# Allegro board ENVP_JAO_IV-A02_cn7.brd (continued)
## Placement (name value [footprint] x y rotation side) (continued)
U124  28 PINP LM5176RHFR  [VQFN28F-5X4X1M]  32.35 106.35 0 top
U126  PP4B10BK,  [TS-MOSFET5X6X1P2]  28.19 118.55 90 top
U127  TPS7B8533QWDRCRQ1  [VSON10F-3X3X1M]  46.55 109.22 180 top

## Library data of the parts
C40-C43 C50-C52 C57 C58 C64 C70-C73 C76 C77 C82 C84 C122 C125 C126 C396-C403 C408 C412-C426 C472 C497 C500-C516 C568 C569 C604 C605 C618-C622 C635 C636 = 11-CAP1-2P0: Tolerance: TOL**; User Part Number: USER**
C44 C45 C498 C499 = 11-CAP-2P0: Tolerance: TOL**; User Part Number: USER**
C46-C49 C55 C56 C59-C63 C65-C69 C104-C117 C119-C121 C123 C124 C244 C380 C382 C454 C456 C457 C459 C461 C466-C468 C471 C473 C475-C478 C489 = 11-CAP1-2P0: User Part Number: USER**; Tolerance: TOL**
C53 C54 C103 C118 C495 C496 = 11-CAP-2P0: User Part Number: USER**; Tolerance: TOL**
CN1 = 1652-PC-3P-ECH381RM03PBK: User Part Number: USER**; Tolerance: TOL**
CN19 = 1653-PH-4P*1-0: User Part Number: USER**; Tolerance: TOL**
CN35 = HL-VGA-9MX2
D1 = 130-S2P-SS1060HEWS-0: User Part Number: USER**; Tolerance: TOL**
D2 = 130-S2P-PMEG2010AEB-0: Tolerance: TOL**; User Part Number: USER**
D3 = 130-S2P-SBM56LAFC-0: User Part Number: USER**; Tolerance: TOL**
D4 = 130-S3P-BAT54CW-0: Tolerance: TOL**; User Part Number: USER**
D6 D7 D49 = 130-E_D2P-TV50C360JBCRHF-0: User Part Number: USER**; Tolerance: TOL**
D9 D13 = 130-D2P-1N4148WS-0: User Part Number: USER**; Tolerance: TOL**
D28 D29 = 130-S2P-SBM56LAFC-0: Tolerance: TOL**; User Part Number: USER**
D31 = 130-S2P-SS1060HEWS-0: Tolerance: TOL**; User Part Number: USER**
D50-D59 = SMBJ18CA: Tolerance: TOL**; User Part Number: USER**
FB1 = 121-FB-2P: User Part Number: USER**; Tolerance: TOL**
H2 = MH: User Part Number: USER**; Tolerance: TOL**
HM3 = S-SO-MH276D167-PTH: User Part Number: USER**; Tolerance: TOL**
L1 L3 L4 = 121-L_COIL-2P: User Part Number: USER**; Tolerance: TOL**
L6 L40 L41 = 121-L_COIL-2P: Tolerance: TOL**; User Part Number: USER**
M2 = S-SO-MH197D138-1-PTH: Tolerance: TOL**; User Part Number: USER**
NOREF NOREF#4 NOREF#6 NOREF#7 = -: User Part Number: USER**; Tolerance: TOL**
NOREF#2 = -: Tolerance: TOL**; User Part Number: USER**
Q3 Q4 Q8 Q17 Q40 Q41 Q52 Q67 = 131-N_MOS3P-NTS4001N-0: User Part Number: USER**; Tolerance: TOL**
Q6 = 131-PN_MOS8P-P0706BK: User Part Number: USER**; Tolerance: TOL**
Q7 = 131-PN_MOS8P-P0706BK: Tolerance: TOL**; User Part Number: USER**
Q9 Q15 Q16 Q18-Q20 Q38 = 131-N_MOS3P-NTS4001N-0: Tolerance: TOL**; User Part Number: USER**
Q12 Q13 = 131-D_N8P-BSC0925ND-0: User Part Number: USER**; Tolerance: TOL**
Q14 = 131-N_MOS6P-PJX138KAR100001-0: User Part Number: USER**; Tolerance: TOL**
Q21 Q62 Q63 = 131-PP_MOS8P-FDS6681Z-0: User Part Number: USER**; Tolerance: TOL**
Q64 Q68 = 131-N_MOS9P-PG1H10ATL: Tolerance: TOL**; User Part Number: USER**
Q65 = 131-N_MOS8P-P0406AK-0: Tolerance: TOL**; User Part Number: USER**
Q66 = 131-NPN3P-MMBT3904W-0: Tolerance: TOL**; User Part Number: USER**
Q73 = 131-N_MOS8P-DMT10H015LCG-0: Tolerance: TOL**; User Part Number: USER**
R23 R24 R27-R29 R37 R41 R43 R44 R50 R51 R63 R64 R66-R70 R97 R112 R113 R119 R339 R425 R457 R459 R469 R470 R477 R479 R497 R501-R503 R513 R515 R521-R527 R529 R546-R561 R687-R704 R706-R708 R782 R801 R803 R815 R841-R845 R848-R851 = 10-R: Tolerance: TOL**; User Part Number: USER**
R30-R36 R38-R40 R42 R45-R49 R52-R61 R72 R73 R91-R96 R98-R111 R114-R118 R120-R122 R304 R455 R462 R463 R480 R481 R608 R610 R612 R617 R620 R624 R625 R649 R651-R658 R663 R665 R667 R671 R674 R682 R705 R738 R739 R758-R760 = 10-R: User Part Number: USER**; Tolerance: TOL**
TP32-TP34 TP98 = TestPoint: Tolerance: TOL**; User Part Number: USER**
TP36 TP48 TP49 TP54-TP59 TP62 TP66 TP67 TP91 TP92 TP101 = TestPoint: User Part Number: USER**; Tolerance: TOL**
U2 = 14-P_R-MIC2128YMLTR-0: User Part Number: USER**; Tolerance: TOL**
U3 U117 = 14-P_R-MP2384GG-0: User Part Number: USER**; Tolerance: TOL**
U8 = 14-P_R-LM5176RHFR-0: User Part Number: USER**; Tolerance: TOL**
U77 = 14-T_C_L-SN74LVC1G11DCKR-0: Tolerance: TOL**; User Part Number: USER**
U97 U99 = 14-T_C_L-SN74AUP1G04DRLR-0: Tolerance: TOL**; User Part Number: USER**
U98 U100 U101 = 14-T_C_L-SN74LVC1G126DCKR-0: User Part Number: USER**; Tolerance: TOL**
U102 U104 = 14-T_C_L-SN74LVC1G11DCKR-0: User Part Number: USER**; Tolerance: TOL**
U103 = 14-T_C_L-74LVC1G86SE-7: User Part Number: USER**; Tolerance: TOL**
U107 = CYPD4226-40LQXIT: Tolerance: TOL**; User Part Number: USER**
U108 = 14-P_R-TPS2051BDBVR-0: User Part Number: USER**; Tolerance: TOL**
U124 = 14-P_R-LM5176RHFR-0: Tolerance: TOL**; User Part Number: USER**
U126 = 131-N_MOS8P-PP4B10BK-0: Tolerance: TOL**; User Part Number: USER**
U127 = TPS7B8533QWDRCRQ1: Tolerance: TOL**; User Part Number: USER**

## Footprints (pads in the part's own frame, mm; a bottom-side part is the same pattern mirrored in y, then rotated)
C0402
  oval 0.61x0.711 smd: 1(-0.457,0) 2(0.457,0)
C0402_PLUS
  oval 0.61x0.711 smd: 1(-0.457,0) 2(0.457,0)
C0603
  rect 0.889x1.016 smd: 1(-0.775,0) 2(0.775,0)
C0805
  rect 1.016x1.524 smd: 1(-0.914,0) 2(0.914,0)
C1206
  oval 1.067x1.803 smd: 1(-1.524,0) 2(1.524,0)
C1210
  oval 1.067x2.692 smd: 1(-1.524,0) 2(1.524,0)
C1808
  oval 1.372x2.21 smd: 1(-2.021,0) 2(2.022,0)
CD8P35-1
  rect 1.422x1.422 hole 0.914: 1(-1.75,0)
  round 1.422 hole 0.914: 2(1.75,0)
DB_HL-VGA9MX2-H28_43MM
  rect 1.6x1.6 hole 1.092: 1(-5.54,9.75) 10(-5.54,2.84)
  round 1.6 hole 1.092: 2(-2.77,9.75) 3(0,9.75) 4(2.77,9.75) 5(5.54,9.75) 6(-4.155,6.91) 7(-1.385,6.91) 8(1.385,6.91) 9(4.155,6.91) 11(-2.77,2.84) 12(0,2.84) 13(2.77,2.84) 14(5.54,2.84) 15(-4.155,0) 16(-1.385,0) 17(1.385,0) 18(4.155,0)
  round 3.708 hole 3.2: H1(-12.495,8) H2(12.495,8) H3(-12.495,0) H4(12.495,0)
DFN8E-3P3X3P3X0P85M
  rect 0.432x0.711 smd: 1(-0.975,-1.406) 2(-0.325,-1.406) 3(0.325,-1.406) 4(0.975,-1.406)
  custom 0.538x0.538 smd: 5(0,0)
ESD-2P-SMA
  rect 1.397x1.651 smd: 1(-2.015,0) 2(2.015,0)
JH4-HD
  rect 1.397x1.397 hole 0.889: 1(-3.81,0)
  round 1.397 hole 0.889: 2(-1.27,0) 3(1.27,0) 4(3.81,0)
L1206
  oval 1.067x1.803 smd: 1(-1.524,0) 2(1.524,0)
MH197D138-1
  round 5.004 hole 3.505: 1(0,0)
MH217D138
  round 5.512 hole 3.505: 1(0,0)
MH276D150-T4P05M
  round 4.699 hole 3.81: 1(0,0)
QFN11F-2X2X1M
  rect 1.499x0.254 smd: 1(-0.55,0.25) 6(0.55,-0.25)
  rect 0.254x0.711 smd: 2(-0.75,-1) 3(-0.25,-1) 4(0.25,-1) 5(0.75,-1) 8(0.75,1) 9(0.25,1) 10(-0.25,1) 11(-0.75,1)
  rect 0.711x0.254 smd: 7(0.95,0.25)
QFN16F-3X3-8
  rect 0.406x0.254 smd: 1(-1.36,0.75) 2(-1.36,0.25) 3(-1.36,-0.25) 4(-1.36,-0.75) 9(1.36,-0.75) 10(1.36,-0.25) 11(1.36,0.25) 12(1.36,0.75)
  rect 0.254x0.406 smd: 5(-0.75,-1.36) 6(-0.25,-1.36) 7(0.25,-1.36) 8(0.75,-1.36) 13(0.75,1.36) 14(0.25,1.36) 15(-0.25,1.36) 16(-0.75,1.36)
  rect 1.702x1.702 smd: 17(0,0)
QFN40F-6X6X0P6M
  rect 0.305x0.813 smd: 1(-2.25,-3) 2(-1.75,-3) 3(-1.25,-3) 4(-0.75,-3) 5(-0.25,-3) 6(0.25,-3) 7(0.75,-3) 8(1.25,-3) 9(1.75,-3) 10(2.25,-3) 21(2.25,3) 22(1.75,3) 23(1.25,3) 24(0.75,3) 25(0.25,3) 26(-0.25,3) 27(-0.75,3) 28(-1.25,3) 29(-1.75,3) 30(-2.25,3)
  rect 0.813x0.305 smd: 11(3,-2.25) 12(3,-1.75) 13(3,-1.25) 14(3,-0.75) 15(3,-0.25) 16(3,0.25) 17(3,0.75) 18(3,1.25) 19(3,1.75) 20(3,2.25) 31(-3,2.25) 32(-3,1.75) 33(-3,1.25) 34(-3,0.75) 35(-3,0.25) 36(-3,-0.25) 37(-3,-0.75) 38(-3,-1.25) 39(-3,-1.75) 40(-3,-2.25)
  rect 4.597x4.597 smd: 41(0,0)
R0402
  oval 0.61x0.711 smd: 1(-0.457,0) 2(0.457,0)
R0603
  rect 0.889x1.016 smd: 1(-0.775,0) 2(0.775,0)
R0805
  rect 1.016x1.524 smd: 1(-0.914,0) 2(0.914,0)
R1206
  oval 1.067x1.803 smd: 1(-1.524,0) 2(1.524,0)
R2512-7
  rect 2.997x4.013 smd: 1(-2.15,0) 2(2.15,0)
SCOILA-2P5X2X1P2M
  rect 0.813x2.007 smd: 1(-1,0) 2(1,0)
SCOILA-17X17P9X7M
  rect 12.802x3.759 smd: 1(0,7.475) 2(0,-7.475)
SCOILA-48P5X47
  rect 1.854x1.803 smd: 1(-1.975,0) 2(1.975,0)
SCOILA-73X68
  rect 2.134x3.556 smd: 1(-2.943,0) 2(2.943,0)
SCOILA-115X100-1
  rect 2.794x3.505 smd: 1(-4.75,0) 2(4.75,0)
SCOILA-115X103
  rect 3.861x4.013 smd: 1(-4.175,0) 2(4.175,0)
SOP8B-150
  rect 0.432x1.854 smd: 1(-1.905,-2.578) 2(-0.635,-2.578) 3(0.635,-2.578) 4(1.905,-2.578) 5(1.905,2.578) 6(0.635,2.578) 7(-0.635,2.578) 8(-1.905,2.578)
TBLOCK-3P-RDM-3P81M-T7P2M
  rect 1.829x1.829 hole 1.321: 1(-3.81,0)
  round 1.829 hole 1.321: 2(0,0) 3(3.81,0)
TC-8P3X8P3X10P5M
  rect 4.089x2.108 smd: 1(-3.45,0) 2(3.45,0)
TC-11X10P3X16P5M
  rect 4.394x2.489 smd: 1(-4.35,0) 2(4.35,0)
TC-D
  oval 2.108x2.87 smd: 1(-3.175,0) 2(3.175,0)
TP20
  round 0.508 smd: 1(0,0)
TS-DO214AB
  rect 1.727x3.2 smd: 1(-3.205,0) 2(3.205,0)
TS-MOSFET5X6-1
  rect 0.66x1.016 smd: 1(-1.905,-3.025) 5(1.905,3.025) 6(0.635,3.025) 7(-0.635,3.025) 8(-1.905,3.025)
  custom 0.58x0.58 smd: 2(0.115,-2.371)
  rect 4.013x2.159 smd: 9(0,0.525)
TS-MOSFET5X6X1P2
  rect 0.559x0.864 smd: 1(-1.905,-2.77) 2(-0.635,-2.77) 3(0.635,-2.77) 4(1.905,-2.77)
  custom 1.1x1.1 smd: 5(0,0)
TS-MOSFET-11P68X9P9X2P4M-8P
  rect 0.787x2.794 smd: 1(-4.2,-4.86) 2(-3,-4.86) 3(-1.8,-4.86) 4(-0.6,-4.86) 5(0.6,-4.86) 6(1.8,-4.86) 7(3,-4.86) 8(4.2,-4.86)
  rect 10.211x8.103 smd: 9(0,2.99)
TS-MSOD80
  rect 0.94x1.346 smd: 1(-0.94,0) 2(0.94,0)
TS-SC70_5-4
  rect 0.356x0.864 smd: 1(-0.65,-1.1) 2(0,-1.1) 3(0.65,-1.1) 4(0.65,1.1) 5(-0.65,1.1)
TS-SC70_6-1
  rect 0.406x0.914 smd: 1(-0.65,-1.1) 2(0,-1.1) 3(0.65,-1.1) 4(0.65,1.1) 5(0,1.1) 6(-0.65,1.1)
TS-SMAF-4P7X2P5X1P1M
  rect 1.6x2.159 smd: 1(-2.15,0) 2(2.15,0)
TS-SOD323-1P8X0P6X0P75M
  rect 2.007x1.118 smd: 1(-0.95,0)
  rect 0.813x1.016 smd: 2(0.95,0)
TS-SOD523-5
  rect 0.508x0.61 smd: 1(-0.7,0) 2(0.7,0)
TS-SOT23_5
  rect 0.61x1.016 smd: 1(-0.94,-1.346) 2(0,-1.346) 3(0.94,-1.346) 4(0.94,1.346) 5(-0.94,1.346)
TS-SOT323
  rect 0.584x0.94 smd: 1(-0.65,-1.158) 2(0.65,-1.158) 3(0,1.158)
TS-SOT323-2X1P25X1M
  rect 0.711x0.914 smd: 1(-0.65,-0.95) 2(0.65,-0.95) 3(0,0.95)
TS-SOT323-2X1P25X1P1M
  rect 0.66x0.864 smd: 1(-0.65,-0.925) 2(0.65,-0.925) 3(0,0.925)
TS-SOT353_5-T1P1M
  rect 0.432x0.61 smd: 1(-0.65,-0.95) 2(0,-0.95) 3(0.65,-0.95) 4(0.65,0.95) 5(-0.65,0.95)
TS-SOT553_5-1P7X1P3X0P6M
  rect 0.305x0.457 smd: 1(-0.5,-0.675) 2(0,-0.675) 3(0.5,-0.675) 4(0.5,0.675) 5(-0.5,0.675)
TS-SOT563_6-4
  rect 0.33x0.432 smd: 1(-0.5,-0.675) 2(0,-0.675) 3(0.5,-0.675) 4(0.5,0.675) 5(0,0.675) 6(-0.5,0.675)
unnamed
  round 1.016 smd: 1(0,0)
unnamed#2
  round 3.988 hole 3.988 unplated: (0,0)
VQFN28F-5X4X1M
  rect 0.229x0.61 smd: 1(-1.75,-1.9) 2(-1.25,-1.9) 3(-0.75,-1.9) 4(-0.25,-1.9) 5(0.25,-1.9) 6(0.75,-1.9) 7(1.25,-1.9) 8(1.75,-1.9) 15(1.75,1.9) 16(1.25,1.9) 17(0.75,1.9) 18(0.25,1.9) 19(-0.25,1.9) 20(-0.75,1.9) 21(-1.25,1.9) 22(-1.75,1.9)
  rect 0.61x0.229 smd: 9(2.4,-1.25) 10(2.4,-0.75) 11(2.4,-0.25) 12(2.4,0.25) 13(2.4,0.75) 14(2.4,1.25) 23(-2.4,1.25) 24(-2.4,0.75) 25(-2.4,0.25) 26(-2.4,-0.25) 27(-2.4,-0.75) 28(-2.4,-1.25)
  rect 3.556x2.54 smd: 29(0,0)
VSON10F-3X3X1M
  rect 0.61x0.254 smd: 1(-1.4,1) 2(-1.4,0.5) 3(-1.4,0) 4(-1.4,-0.5) 5(-1.4,-1) 6(1.4,-1) 7(1.4,-0.5) 8(1.4,0) 9(1.4,0.5) 10(1.4,1)
  custom 0.414x0.414 smd: 11(0,0)

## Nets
3V3_AO: C382.1 R64.2 R455.1 R462.2 R469.1 R470.1 R501.1 R548.1 U77.5
3V3_AO_BODE: C84.1 R66.2 R67.1
3V3_AO_BOOT: C77.1
3V3_AO_EN: R63.2
3V3_AO_FB: R70.1
3V3_AO_FB_R: C84.2 R67.2 R68.1 R70.2
3V3_AO_SW: C77.2 L4.2(P2)
3V3_PD_EN: R459.2 U127.8
3V3_PG_DELAY: C515.1 U127.4
3V3_PVDD: C48.1 R34.1 U2.8
3V3_VDD: C49.1 R34.2 R38.1 R45.1 U2.15
5V_AO: C76.1 C426.1 R463.1 R549.1 R851.2 U108.5
5V_AO_PG: R63.1
5V_DISCHG_D: Q4.3 R27.2 R28.2
5V_ON_D: Q3.3 Q4.1
12V_SYS_EN: Q15.1 R95.2 R108.1 U8.26
12V_SYS_EN_N: D4.2 Q15.3 R96.2
12V_VISNS: R477.2 U8.28
+3V3A_L: C50.1 C51.1 C52.1 C53.1 C54.1 L1.1 R37.1 R43.1 R46.1
AVDD_CAM_2V8: R652.2
GND: C40.2 C41.2 C42.2 C43.2 C44.2 C45.2 C46.2 C48.2 C50.2 C51.2 C52.2 C53.2 C54.2 C55.2 C57.2 C60.2 C61.2 C63.2 C64.2 C65.2 C66.1 C68.2 C70.2 C71.2 C72.2 C73.2 C76.2 C82.1 C103.2 C104.1 C105.1 C106.1 C107.2 C108.2 C110.2 C112.2 C114.2 C115.2 C116.2 C117.2 C118.2 C119.2 C120.2 C121.2 C125.2 C382.2 C396.2 C397.2 C398.2 C399.2 C400.2 C401.2 C402.2 C403.2 C408.2 C412.2 C413.2 C414.2 C415.2 C416.2 C417.2 C418.1 C419.2 C420.2 C421.2 C422.2 C423.2 C424.2 C425.2 C426.2 C454.1 C457.2 C461.2 C466.2 C467.2 C468.2 C472.2 C473.1 C475.2 C476.1 C477.2 C489.2 C495.2 C496.2 C497.1 C498.2 C499.2 C500.2 C501.2 C503.2 C504.1 C508.1 C509.1 C510.2 C511.2 C512.2 C513.2 C514.2 C515.2 C516.2 C568.2 C569.2 C604.2 C635.2 C636.2 CN19.4 CN35.5 CN35.14 D50.1 D51.1 D52.1 D53.1 D54.1 D55.1 D56.1 D57.1 D58.1 D59.1 Q3.2(SOURCE) Q4.2(SOURCE) Q7.1 Q7.2 Q7.3(S3) Q8.2(SOURCE) Q9.2(SOURCE) Q14.4(SOURCE) Q15.2(SOURCE) Q16.2(SOURCE) Q17.2(SOURCE) Q18.2(SOURCE) Q19.2(SOURCE) Q20.2(SOURCE) Q38.2(SOURCE) Q40.2(SOURCE) Q41.2(SOURCE) Q66.2(E) Q67.2(SOURCE) Q73.1 Q73.2 Q73.3(S3) R24.2 R50.1 R57.2 R68.2 R91.1 R94.2 R102.2 R104.2 R113.2 R114.2 R118.2 R457.1 R481.1 R503.2 R513.1 R522.2 R524.2 R527.2 R554.2 R556.2 R561.2 R658.2 R682.1 R687.1 R693.2 R697.2 R698.2 R703.2 R707.1 R815.2 R848.2 R849.2 U2.6 U3.2 U3.3 U3.4 U3.9 U8.7 U8.10 U8.11 U8.19 U8.29 U77.2 U97.3 U98.3 U99.3 U100.3 U101.3 U102.2 U103.3 U104.2 U107.41 U108.2 U117.2 U117.3 U117.4 U117.9 U124.7 U124.19 U124.29 U127.6 U127.11
GND_+3V3A_L: C49.2 C59.2 C62.2 R31.2 R47.2 R49.2 R50.2 U2.14 U2.17
GND_EARTH: C123.2 C124.1 CN1.1 D6.1 D7.1 H2.1
V5V_EN: R549.2 U108.4
V5V_OC#: R548.2 TP67.1(TP) U108.3
V5V_P1: C419.1 C420.1 R553.1 U107.8 U108.1(OUT)
VBUS1_EN_R: R529.1 TP62.1(TP)
VBUS1_ENABLE_CONSUMER: R529.2
VBUS_C_CTRL_OR: TP58.1(TP) U103.4(Y) U104.1
VBUS_C_CTRL_P1: R521.2 R522.1 U100.2 U102.1 U107.12
VBUS_C_CTRL_P1_R: TP55.1(TP) U100.4(Y) U103.2
VBUS_C_CTRL_P2: R523.2 R524.1 R546.2 U101.2 U102.3 U107.38
VBUS_C_CTRL_P2_R: R547.2 TP56.1(TP) U101.4(Y) U103.1
VBUS_DISCHARGE_P1: U107.20
VBUS_MON_P1: C425.1 R555.2 R556.1 U107.13
VBUS_P_CTRL_P1: U107.11
VCC_DCIN: C498.1 C499.1 C500.1 C501.1 D9.1 Q62.5 Q62.6 Q62.7 Q62.8 Q68.9 R694.1 R696.2 R702.2 R841.1 R845.1
VCC_DCIN+: C122.1 C123.1 C495.1 C496.1 C568.1 C569.1 CN1.2 D6.2(CATHODE) D31.2 D49.2(CATHODE) Q64.9 R112.1 R425.2 R700.1 R801.1 R803.1
VCC_DCIN-: C122.2 C124.2 CN1.3 D7.2(CATHODE) D49.1 Q73.5
VCC_DCIN_EN: C504.2 Q66.1 Q67.3 R702.1 R703.1
VCC_DCIN_EN_MID: Q66.3 R699.2
VCC_DCIN_EN_N: C502.2 C622.2 Q62.4 Q63.4 R695.2 R699.1
VCC_DCIN_PG: R803.2 TP101.1(TP) U124.14
VCC_DCIN_Q: C502.1 C622.1 Q62.1 Q62.2 Q62.3(SOURCE_2) Q63.1 Q63.2 Q63.3(SOURCE_2) R695.1
VCC_SRC: C40.1 C41.1 C42.1 C43.1 C44.1 C45.1 C63.1 C64.1 C65.1 C118.1 C119.1 C120.1 C121.1 C489.1 D1.2 Q6.5 Q12.2 Q21.5 Q21.6 Q21.7 Q21.8 R30.1 R32.1 R115.1 R121.1 R122.1 R477.1 U3.1(VIN)
VCC_SRC_FET: C126.1 C380.1 C503.1 C621.1 Q21.1 Q21.2 Q21.3(SOURCE_2) Q63.5 Q63.6 Q63.7 Q63.8 R119.1 R705.1 TP91.1(TP)
VCCD_1V8: C418.2 U107.33
VDD1: C457.1
VDD12V_DISCHARGE: D4.3(D3) Q16.1 R109.2
VDD_1V8: Q14.2 Q52.1 R59.2 R60.1 R61.1 R105.1 R480.2 R551.1
VDD_1V8_DISCHARGE: Q9.3 R60.2 R61.2
VDD_1V8_PG: R72.2 U3.5
VDD_3V3: C466.1 C467.1 R29.1 R37.2 R51.1 R73.1 R502.1 R550.1 R617.2 R620.2 R649.1 R671.2 R674.2
VDD_3V3_DISCHARGE: Q8.3 R29.2 R51.2
VDD_3V3_EN: R106.1 U2.10
VDD_3V3_PD: C396.1 C397.1 C398.1 C399.1 C400.1 C401.1 C402.1 C403.1 C414.1 C415.1 C416.1 C417.1 R339.1 R525.1 R526.1 R546.1 R547.1 R552.1 R557.1 R558.1 R559.1 R560.1 R704.1 R706.1 R708.2 R782.1 R850.2 TP66.1(TP) U97.5 U98.5 U99.5 U100.5 U101.5 U102.5 U103.5 U104.5 U107.31 U107.32 U127.1(VOUT)
VDD_3V3_PD_PG: R708.1 TP92.1(TP) U127.7
VDD_3V3_PD_PGADJ: R706.2 R707.2 U127.2
VDD_3V3_PG: R38.2 R53.1 U2.1 U107.4
VDD_5V: C468.1 C635.1 C636.1 R27.1 R28.1 R95.1 R96.1 R107.1 R109.1 U117.1(VIN)
VDD_12V: FB1.2 R110.1 R111.1
VDD_12V_DISCHARGE: Q16.3 R110.2 R111.2
VDD_12V_ENABLE: Q14.3 R108.2
VDDD_IN_CCG4: C408.1 C412.1 C413.1 D9.2 D13.2 R459.1 U127.10
VIN_PWR_ON: R23.1 R117.2 R502.2
VIN_PWR_ON_5V: Q3.1 R23.2 R24.1
VIN_PWR_ON_SRC: Q19.1 R117.1 R118.1
VSS1: C461.1
VSS2: C475.1
BRD_SEL: R501.2
CAM_2V8_BODE: C478.1 R655.2 R656.1
CAM_2V8_BOOT: C471.1 U117.7
CAM_2V8_EN: R651.2 U117.11
CAM_2V8_FB: R657.1 U117.10
CAM_2V8_FB_R: C478.2 R656.2 R657.2 R658.1
CAM_2V8_PG: R653.2 U117.5
CAM_2V8_SNUB: C477.1 R654.2
CAM_2V8_SW: C471.2 L40.2(P2) R654.1 U117.6
CAM_AVDD_EN: R651.1
CAM_SPI_CS0: TP98.1(TP)
CAN0_DIN: R759.2
CAN0_DOUT: R758.2
CAN_BUS_SET: R760.2
CARRIER_POWER_ON: Q18.1 R52.1 R106.2 R497.2
CARRIER_SHUTDOWN_N: Q38.3 R463.2 TP33.1(TP) U77.3
CCG4_LED: U107.6
COM1_SET: R738.2
COM2_SET: R739.2
CTS1: CN35.17 D50.2(CATHODE)
CTS2: CN35.8 D55.2(CATHODE)
CVM_PRSNT: Q38.1 R455.2
D1-: CN35.10 D54.2(CATHODE) R608.2
D2-: CN35.1 D59.2(CATHODE) R663.2
DC_IN_EC: C125.1 Q17.1 R112.2 R113.1
DC_IN_EC_N: Q17.3 R560.2 U107.34
DC_IN_GATE_CCG4: R339.2 U97.2 U98.2 U99.2 U107.35
DC_IN_GATE_CCG4_CTRL: Q67.1 R704.2 TP54.1(TP) U98.4(Y) U100.1 U101.1
DC_IN_GATE_OE: U98.1 U102.4(Y)
DCIN+_20V_EN: R700.2 U124.26
DCIN+_VIN: C516.1 R701.1 U124.27
DCIN+_VISNS: R425.1 U124.28
DISCHARGE: D4.1 Q8.1 Q9.1 R116.1
DISCHARGE_CAR: Q18.3 R114.1 R115.2 R116.2
EFM8_FORCE_SHUTDOWN: TP32.1(TP) U77.4(Y)
EFM8_P0_4: TP48.1(TP)
EFM8_PSHOLD: R497.1
EFM8_RST_MON: Q41.3 R470.2 TP36.1(TP)
ENABLE1: R617.1
ENABLE2: R671.1
GPIO_PMOS_ON: R561.1 TP57.1(TP) U104.3 U107.36
GPIO_PMOS_ON_CTRL: R527.1 TP59.1(TP) U104.4(Y)
HDMI_GND: C508.2 CN35.H1 CN35.H2 CN35.H3 CN35.H4 R457.2
I2C_GP2_CLK_3V3: U107.17
I2C_GP2_DAT_3V3: U107.16
I2C_GP8_CLK: R738.1
I2C_GP8_DAT: R739.1
I2C_INT_CCG4: Q52.2(SOURCE) R551.2
I2C_INT_CCG4_3V3: Q52.3 R550.2 U107.15
IRQ_PD_N: R782.2 U107.26
JTAG_TRST_N: R480.1 R481.2
MIC2128_3V3_DH: Q6.4 R35.1
MIC2128_3V3_DL: C61.1 Q7.4 R40.1
MIC2128_3V3_SW: C47.2 L1.2(P2) Q6.1 Q6.2 Q6.3(S3) Q7.5 R36.1 R39.1 R41.1 R42.1
MOD_SHUTDOWN_N_3V3: TP34.1(TP) U77.1
MOD_TEMP_SHDN_EN_N: R682.2
MODULE_POWER_ON: R503.1
OCP_USBC1_N: R557.2 U107.5
PCIE_12V_EN_N: Q14.1 R105.2
PD_FW_PWR: CN19.1 R850.1 R851.1
PD_SWD_CLK: CN19.2 U107.2
PD_SWD_IO: CN19.3 U107.1
PEX_TX14_N: C244.2
PS_1V8_BODE: C69.1 R55.2 R56.1
PS_1V8_BOOT: C67.1 U3.7
PS_1V8_EN: R52.2 R53.2 U3.11
PS_1V8_FB: R54.1 U3.10
PS_1V8_FB_R: C69.2 R54.2 R56.2 R57.1
PS_1V8_PG: R72.1 R73.2
PS_1V8_SNUB: C68.1 R58.2
PS_1V8_SW: C67.2 L3.2(P2) R58.1 U3.6
PS_12_CS: C605.2 Q12.5 Q12.6 Q12.7(S2_2) Q13.5 Q13.6 Q13.7(S2_2) R94.1 R515.2
PS_12V_BIAS: C114.1 R842.2 U8.21
PS_12V_BODE: C107.1 R92.2
PS_12V_BOOT1: C111.2 D3.1 U8.23
PS_12V_BOOT2: C113.2 D2.1 U8.17
PS_12V_COMP: C108.1 R92.1 U8.6
PS_12V_CS: C109.1 R515.1 U8.13
PS_12V_CSG: C109.2 R815.1 U8.12
PS_12V_DITH: C104.2 U8.2
PS_12V_FB: R103.1 R104.1 U8.8
PS_12V_HDRV1: R97.2 U8.24
PS_12V_HDRV2: R99.2 U8.16
PS_12V_HG1: Q12.1 R97.1
PS_12V_HG2: Q13.1 R99.1
PS_12V_LDRV1: R98.2 U8.22
PS_12V_LDRV2: R100.2 U8.18
PS_12V_LG1: Q12.8 R98.1
PS_12V_LG2: Q13.8 R100.1
PS_12V_MODE: R102.1 U8.1
PS_12V_OUT: C103.1 C115.1 C116.1 C117.1 FB1.1 Q13.2 R101.1 R103.2 R842.1 R843.1
PS_12V_RT: R91.2 U8.3
PS_12V_SLOPE: C105.2 U8.4
PS_12V_SS: C106.2 U8.5
PS_12V_SW1: C111.1 L6.2(P2) Q12.9 R69.1 U8.25
PS_12V_SW2: C113.1 C618.2 L6.1 Q13.9 U8.15
PS_12V_VCC: C112.1 D2.2 D3.2 U8.20
PS_12V_VIN: C110.1 R93.2 U8.27
PS_12V_VIN_D: D1.1 R93.1
PS_12V_VOSNS: R101.2 U8.9(VOSNS)
PS_20_CS: C619.2 Q65.1 Q65.2 Q65.3(S3) R479.1 R698.1 U126.1 U126.2 U126.3(S3)
PS_20V_BIAS: C510.1 R841.2 U124.21
PS_20V_BODE: C513.1 R688.2
PS_20V_BOOT1: C506.2 D28.1 U124.23
PS_20V_BOOT2: C507.2 D29.1 U124.17
PS_20V_COMP: C512.1 R688.1 U124.6
PS_20V_CS: C505.2 R479.2 U124.13
PS_20V_CSG: C505.1 R513.2 U124.12
PS_20V_DITH: C497.2 U124.2
PS_20V_FB: R694.2 R697.1 U124.8
PS_20V_HDRV1: R689.1 U124.24
PS_20V_HDRV2: R692.1 U124.16
PS_20V_HG1_2: Q64.1 R689.2
PS_20V_HG2: Q68.1 R692.2
PS_20V_LDRV1: R690.1 U124.22
PS_20V_LDRV2: R691.1 U124.18
PS_20V_LG1: R690.2 U126.4
PS_20V_LG2: Q65.4 R691.2
PS_20V_MODE: R693.1 U124.1
PS_20V_RT: R687.2 U124.3
PS_20V_SLOPE: C511.1 U124.4
PS_20V_SS: C509.2 U124.5
PS_20V_SW1: C506.1 L41.1 Q64.2 Q64.3 Q64.4 Q64.5 Q64.6 Q64.7 Q64.8(S7) R844.1 U124.25 U126.5
PS_20V_SW2: C507.1 C620.2 L41.2(P2) Q65.5 Q68.2 Q68.3 Q68.4 Q68.5 Q68.6 Q68.7 Q68.8(S7) U124.15
PS_20V_VCC: C514.1 D28.2 D29.2 U124.20
PS_20V_VOSNS: R696.1 U124.9(VOSNS)
RS232_RD1: R610.1
RS232_RD2: R665.1
RS232_TD1: R612.1
RS232_TD2: R667.1
RS485_D1-: R608.1
RS485_D2-: R663.1
RTS1: CN35.16 D52.2(CATHODE)
RTS2: CN35.7 D57.2(CATHODE)
RX1/D1+: CN35.11 D53.2(CATHODE) R610.2
RX2/D2+: CN35.2 D58.2(CATHODE) R665.2
SNN_CY14_RESERVED: U107.14
SNN_CY21_RESERVED: U107.21
SNN_EFM8SB10_P0_5: TP49.1(TP)
SNN_PD_VR_ENABLE: U107.27
SNN_USBC1_CC1_DUT: U107.22
SNN_USBC1_CC2_DUT: U107.24
SNN_USBC2_MUX_CTRL_N: R559.2 U107.28
SNN_USBC2_ORIENTATION: U107.30
SNN_VBUS_DISCHARGE_P2: U107.40
SNN_VBUS_MON_P2: R848.1 U107.37
SNN_VBUS_P_CTRL_P2: U107.39
SNN_VCONN_MON_P2: R849.1 U107.25
SNN_VIN_ADJ: U107.3
SOC_CAN0_DIN: R759.1
SOC_CAN0_DOUT: R758.1
SOC_CAN1_DOUT: R760.1
SP339_5V: C454.2 C473.2
SP339_UART2_RTS: R304.2
SP339_UART2_RX: R625.2
SP339_UART2_TX: R624.2
SRC_ON_D: Q19.3 Q20.1 R120.2
SRC_SW_G: C126.2 C621.2 Q21.4 R119.2 R120.1
SYS_RST_IN_N: Q40.1
SYS_RST_IN_Q: Q40.3 Q41.1 R469.2
TX1: CN35.12 D51.2(CATHODE) R612.2
TX2: CN35.3 D56.2(CATHODE) R667.2
UART2_RTS: R304.1
UART2_RX: R625.1
UART2_TX: R624.1
UPHY_TX9_N: C244.1
USBC1_CC1_DUT: C422.1 U107.9
USBC1_CC2_DUT: C423.1 U107.7
USBC1_MUX_CTRL_N: R558.2 U107.29
USBC1_ORIENTATION: U107.18
USBC1_VBUS: D13.1 R555.1
VCONN_MON_P1: C424.1 R553.2 R554.1 U107.19
XRES: C421.1 R552.2 U107.10(XRES)
N7364585: R31.1 R32.2 U2.11
N7364615: C46.1 R30.2 U2.16(VIN)
N7364639: C58.1 R43.2 R44.1
N7364653: C60.1 R46.2 U2.9
N7364665: C59.1 R45.2 R47.1 U2.12
N7364675: R48.1 U2.13
N7364759: C47.1 R33.1
N7364853: C56.2 C58.2 C62.1 R44.2 R48.2 R49.1
N7364927: R40.2 U2.7
N7364931: C55.1 R39.2 U2.2
N7365093: C56.1 R42.2
N7365097: C57.1 R41.2
N7366211: R33.2 U2.4
N7366215: R35.2 U2.5
N7366231: R36.2 U2.3
N7371396: C66.2 U3.8
N7372642: C70.1 C71.1 C72.1 C73.1 L3.1 R55.1 R59.1
N7382435: C82.2
N7382555: L4.1 R64.1 R66.1
N7434344: Q14.5 Q14.6 R107.2
N7440074: Q20.3 R121.2 R122.2
N7802848: C380.2 R705.2
N7804391: R462.1 U77.6
N7854424: R521.1 U97.4(Y)
N7855347: R523.1 U99.4(Y)
N7856574: R525.2 U102.6
N7893694: R526.2 U104.6
N8090559: C456.2
N8090595: C456.1
N8090599: C459.2
N8090635: C459.1
N8090819: R620.1
N8148227: R649.2 R653.1
N8148339: C476.2 U117.8
N8148459: C472.1 C604.1 L40.1 R652.1 R655.1
N8158949: R674.1
N8239387: D31.1 R701.2
N8694423: Q73.4 R801.2
N10120133: C605.1 R69.2
N10120570: C618.1 R843.2
N10120736: C619.1 R844.2
N10120879: C620.1 R845.2

Pads without a net: CN35 4 6 9 13 15 18; HM3 1; M2 1; NOREF 1; NOREF#4 1; NOREF#6 1; NOREF#7 1; U8 14; U97 1; U99 1; U107 23; U124 10 11; U127 3 5 9

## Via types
v1: diameter 0.508, hole 0.305, TOP to BOTTOM, 3783 vias
v2: diameter 0.254, hole 0.102, TOP to L2-GND1, 257 vias
v3: diameter 0.254, hole 0.102, L2-GND1 to L3-IN1, 224 vias
v4: diameter 0.356, hole 0.203, L3-IN1 to L6-IN2, 41 vias
v5: diameter 0.254, hole 0.102, L6-IN2 to L7-GND2, 464 vias
v6: diameter 0.254, hole 0.102, L7-GND2 to BOTTOM, 621 vias
v7: diameter 0.406, hole 0.254, TOP to BOTTOM, 116 vias

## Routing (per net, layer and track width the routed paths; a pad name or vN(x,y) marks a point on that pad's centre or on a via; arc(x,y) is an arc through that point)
3V3_AO: length 139.5
  TOP w0.508: R548.1 v1(48.21,84.28)
  L3-IN1 w0.508: v1(94.36,79.22) 93.37,78.23 91.57,78.23 91.31,78.49 v1(89.53,78.49) 89.53,77.85 87,75.31 76.37,75.31 v1(74.34,77.34) 65.02,77.34 56.9,85.47 48.77,85.47 48.21,84.91 v1(48.21,84.28)
  L6-IN2 w0.381: v1(87.25,113.41) 86.61,113.41 85.47,112.27 83.31,112.27 82.04,111 82.04,106.05 80.9,104.9 80.9,90.17 80.26,89.53 75.56,89.53 74.34,88.31 v1(74.34,77.34)
  BOTTOM w0.203: 90.42,60.66 90.42,61.21 90.56,61.35 90.56,62.91
  BOTTOM w0.381: 87.08,61.96 87.08,61.26 87.12,61.21 87.12,60.66 87.4,60.66 87.93,61.19 v1(87.93,62.8) ; v1(96.72,54.36) 97.16,53.92 97.16,53.67 ; v1(105.66,75.06) 105.79,74.93 105.79,74.24 ; v1(85.85,67.44) 86.28,67.01 R469.1 86.42,66.54 86.42,65.67 R501.1 ; C382.1 90.63,75.51 90.93,75.82 U77.5
  BOTTOM w0.508: 96.01,70.5 96.01,71.68 v1(95,71.68) ; 89.53,76.63 88.32,76.63 87.5,75.82 87.5,72.52 88.14,71.88 90.3,71.88 91.69,70.48 R470.1 92.28,68.91 v1(92.46,69.09) ; 89.53,76.63 R462.2 C382.1 ; 89.53,76.63 v1(89.53,78.49) ; v1(98.81,72.64) 98.55,72.9 98.55,73.33 ; v1(97.92,72.01) 97.59,71.68 97.59,71.37 ; 90.42,60.66 91.57,60.66 91.57,61.53 v1(91.19,61.91) ; v1(86.36,60.71) 85.97,60.71 85.48,60.22 ; 95.33,63.63 95.33,63.42 95.76,62.99 95.76,62.15 95.33,61.72 v1(95.99,61.06)
  vias: v1(80.77,65.85) v1(80.96,66.48) v1(81.41,65.85) v1(81.6,66.48) v1(82.04,65.85) v1(82.23,66.48) v1(82.68,65.85) v1(82.87,66.48) v1(83.31,65.85) v1(83.5,67.82) v1(83.5,67.18) v1(83.5,66.48) v1(102.87,51.31) v1(103.5,51.31) v1(104.14,51.31) v1(107.53,80.78) v1(108.33,50.8) v1(111.12,72.64) v1(111.25,51.82) v1(113.54,72.58) v1(114.68,72.58) v1(116.97,51.44) v1(117.6,51.44) v1(117.6,50.8) v1(118.24,51.44) v1(124.46,51.44) v1(125.09,51.44) v1(125.55,57.86) v1(125.73,51.44) v1(126.36,51.44) v1(127.57,54.17) v1(133.79,57.85) v1(133.99,58.93) v1(133.99,51.31) v1(133.99,50.67) v1(134.62,51.31) v1(134.62,50.67) v1(140.65,51.44) v1(148.34,49.53) v1(157.61,48.9) v1(158.24,48.9) v1(158.24,48.26) v1(158.88,48.9) v1(158.88,48.26)
3V3_AO_BODE: length 2.3
  TOP w0.254: R66.2 R67.1 C84.1
3V3_AO_BOOT: length 2.3
  TOP w0.254: 69.09,65.53 69.09,65.4 68.77,65.4
  TOP w0.508: C77.1 69.93,66.62 69.09,65.79 69.09,65.53
3V3_AO_EN: length 2.3
  TOP w0.102: R63.2 66.17,67.44 67.07,66.54 67.07,66.15
3V3_AO_FB: length 2.1
  TOP w0.254: R70.1 67.31,67.01 67.57,66.75 67.57,66.15
3V3_AO_FB_R: length 3.9
  TOP w0.254: R70.2 C84.2 R67.2 R68.1
3V3_PD_EN: length 1.4
  TOP w0.254: U127.8 44.7,109.22 44.25,109.68 R459.2
3V3_PG_DELAY: length 1.4
  TOP w0.254: C515.1 49.22,109.72 U127.4
3V3_VDD: length 31.7
  TOP w0.254: U2.15 70.55,85.97 70.68,86.11
  TOP w0.508: R38.1 v1(71.12,88.39) ; R34.2 63.37,82.75 63.37,79.38 65.79,76.96 69.09,76.96 71.25,79.12 v1(71.25,79.25) 71.7,79.71 R45.1 ; 70.68,86.11 70.82,86.25 C49.1 72.91,86.25 v1(73.15,86.23)
  BOTTOM w0.508: v1(71.12,88.39) 72.01,88.39 73.15,87.25 v1(73.15,86.23) 73.15,79.76 72.64,79.25 v1(71.25,79.25)
5V_AO: length 60.6
  TOP w0.508: C426.1 43.69,81.47 44.37,82.16 R549.1 ; C426.1 44.77,79.83 U108.5 ; C426.1 44.82,80.91 v1(44.96,80.77) v1(45.59,80.77) ; R851.2 65.02,71.81 v1(65.02,72.01)
  L3-IN1 w0.508: v1(98.16,61.46) 98.16,58.69 96.9,57.43 v1(96.77,57.43) 96.49,57.43 94.87,59.05 85.98,59.05 83.82,61.21 v1(83.46,61.21) 83.06,61.21 81.89,60.05 72.01,60.05 v1(67.31,55.35)
  BOTTOM w0.305: 83.19,61.77 83.37,61.96 84.88,61.96
  BOTTOM w0.381: v1(83.46,61.21) 83.19,61.49 83.19,61.77
  BOTTOM w0.508: R463.1 93.73,71.88 v1(94.49,71.12) 94.87,70.74 94.87,68.58 95.25,68.2 95.25,67.31 96.7,65.86 96.7,62.92 v1(98.16,61.46)
  vias: v1(56.52,61.34) v1(56.52,60.71) v1(56.52,60.07) v1(56.52,58.8) v1(57.15,60.07) v1(57.15,59.44) v1(57.15,58.8) v1(57.78,60.07) v1(57.78,59.44) v1(57.78,58.8) v1(58.42,61.34) v1(58.42,60.71) v1(58.42,60.07) v1(58.42,59.44) v1(58.42,58.8) v1(59.05,61.34) v1(59.05,60.71) v1(59.05,60.07) v1(59.05,59.44) v1(59.69,61.34) v1(59.69,60.71) v1(59.69,60.07) v1(59.69,59.44) v1(60.33,61.34) v1(60.33,60.71) v1(60.33,60.07) v1(62.99,67.94) v1(62.99,67.31) v1(62.99,65.28) v1(63.63,67.94) v1(63.63,67.31) v1(63.63,65.28) v1(64.52,65.91) v1(64.52,65.28) v1(64.64,67.94) v1(64.64,67.31) v1(65.15,65.91) v1(65.28,67.94) v1(65.28,67.31) v1(65.79,65.91) v1(96.77,56.72) v1(96.77,56.08) v1(97.51,55.75) v1(97.51,55.12) v1(98.15,55.75) v1(98.15,55.12) v1(98.81,58.04) v1(98.81,57.4) v1(98.78,55.09) v1(148.34,52.45) v1(149.1,49.53) v1(149.73,49.53) v1(150.24,52.45) v1(150.37,51.82) v1(150.88,52.2)
5V_AO_PG: length 13.8
  TOP w0.102: v1(61.47,59.69) 61.47,68.2 62.61,69.34 65.86,69.34 R63.1
5V_ON_D: length 4.7
  TOP w0.254: Q3.3 56.38,64.71 55.04,63.37 53.98,63.37 53.33,64.02 Q4.1
12V_SYS_EN: length 11.7
  TOP w0.102: U8.26 73.16,111.13 72.52,110.49 72.52,110.03 R108.1 71.15,108.66 68.55,108.66 68.33,108.43 68.33,107.75 R95.2 68.2,106.6 68.2,105.33 Q15.1
12V_SYS_EN_N: length 3.4
  TOP w0.102: Q15.3 65.6,105.6 v1(66.42,106.43) R96.2
  BOTTOM w0.102: D4.2 65.93,105.93 v1(66.42,106.43)
12V_VISNS: length 5.8
  TOP w0.254: U8.28 74.05,109.8 73.85,109.6
  TOP w0.508: 73.85,109.6 73.85,109.28 72.26,107.7 72.26,106.12 R477.2
+3V3A_L: length 68.2
  TOP w0.254: 43.05,91.44 43.05,89.53 43.43,89.15 44.96,89.15 45.72,89.92 58.55,89.92 61.98,86.49 61.98,79.12 65.28,75.82 69.47,75.82 70.94,77.29 R43.1
  TOP w0.508: v1(64.14,82.42) 64.14,82.04 64.72,81.46 R46.1
  BOTTOM w0.508: v1(64.14,82.42) 64.14,86.11 60.07,90.17 45.21,90.17 45.09,90.3 45.09,91.31
  vias: v1(41.91,93.7) v1(41.91,93.07) v1(42.55,93.7) v1(42.8,99.57) v1(43.18,94.72) v1(43.43,99.57) v1(43.81,94.72) v1(44.07,99.57) v1(44.07,98.93) v1(44.07,98.3) v1(44.45,97.16) v1(44.45,96.52) v1(44.45,95.35) v1(44.45,94.72) v1(44.45,93.73) v1(44.45,93.09) v1(44.45,92.46) v1(44.7,99.57) v1(44.7,98.93) v1(44.7,98.3) v1(45.09,97.16) v1(45.09,96.52) v1(45.09,95.35) v1(45.09,94.72) v1(45.09,93.73) v1(45.09,93.09) v1(45.09,92.46) v1(45.34,99.57) v1(45.34,98.93) v1(45.34,98.3)
AGND: length 62.6
  TOP w0.102: v1(177.48,11.49) 177.75,11.76 177.75,12.19
  TOP w0.381: 172.21,4 173.36,5.14 173.36,8.76 174.71,10.12 176.16,10.12 176.83,10.79 176.83,10.62 177.33,10.12 179.03,10.12 179.51,10.6 179.8,10.6 179.99,10.79 179.99,11.02 179.32,11.68 v1(179.32,12.83)
  TOP w0.508: 177.75,10.79 178.24,11.29 v1(178.24,11.49) ; 175.34,10.79 v1(176.02,10.79) ; 174.5,13.39 174.45,13.34 v1(173.74,13.34) 172.72,13.34 172.21,12.83 172.21,12.4 ; v1(181.61,25.78) 181.03,25.78 180.85,25.96
  L2-GND1 w0.508: 162.66,8.3 161.59,8.3 ; 162.66,4.6 161.57,4.6
  L3-IN1 w0.102: v1(178.84,21.97) 178.37,21.5 178.37,12.38 v1(177.48,11.49)
  L4-VCC1 w0.508: 161.54,8.38 161.63,8.3 162.66,8.3 ; 162.66,4.6 161.57,4.6
  L5-VCC2 w0.508: 161.54,8.38 161.63,8.3 162.66,8.3 ; 162.66,4.6 161.57,4.6
  L7-GND2 w0.508: 161.54,8.38 161.63,8.3 162.66,8.3 ; 162.66,4.6 161.6,4.6 161.59,4.6
  BOTTOM w0.102: v1(178.84,21.97) 178.39,22.42 177.75,22.42
  BOTTOM w0.203: 177.75,21.23 178.56,21.23
  BOTTOM w0.381: 182.25,17.83 v1(182.25,16.76) ; 181.36,25.1 v1(182.07,25.1) ; 178.56,21.23 178.67,21.23 v1(178.94,20.95) 179.15,20.75 180.75,20.75 181.2,20.29 v1(181.41,20.29) ; 183.39,17.83 183.39,16.87 181.89,15.37 180.59,15.37 179.32,14.1 v1(179.32,12.83)
  BOTTOM w0.508: v1(182.12,23.24) v1(182.75,23.24) 183.53,22.47 183.53,22.35 ; 179.25,17.35 v1(179.96,17.35) ; 179.27,16.18 179.39,16.07 v1(179.96,16.07) ; v1(175.51,13.46) 175.51,12.65 ; 180.09,25.1 v1(180.09,25.78) ; 180.75,16.13 180.81,16.07 v1(181.48,16.07) ; 180.59,18.52 180.95,18.52 v1(181.23,18.8)
  vias: v1(162.31,10.92) v1(162.31,9.78) v1(162.31,1.4) v1(162.69,22.06) v1(163.45,19.56) v1(165.61,14.61) v1(165.74,22.1) v1(166.62,17.4) v1(167.31,19.43) v1(167.53,22.09) v1(167.64,16.26) v1(169.16,19.43) v1(169.42,14.61) v1(169.66,22.09) v1(170.18,16.26) v1(170.94,20.57) v1(171.7,16.89) v1(171.96,18.29) v1(172.59,1.52) v1(173.48,18.41) v1(173.79,16.81) v1(175.77,16.84) v1(177.27,15.37) v1(177.62,19.43) v1(177.67,12.95) v1(181.48,23.24) v1(182.25,25.78)
GND: length 541.5
  TOP w0.102: 183.18,77.42 183.18,78.16 183.39,78.36 184.15,78.36 184.66,77.85 184.66,77.42 186.49,77.42 v1(187.71,76.2) ; 91.18,126.58 91.18,127.28 90.79,127.67 90.79,127.96 v3(90.94,128.11) ; 97.17,51.95 96.98,51.95 v1(96.33,51.31) ; v3(71.37,54.17) 71.52,54.02 71.52,53.87 71.23,53.57 71.23,53.02 71.12,52.91 ; 185.47,72.26 185.29,72.26 184.66,71.63 183.95,71.63 ; 185.47,72.26 185.47,73.74 185.17,74.04 183.39,74.04 183.18,74.24 183.18,75.36 183.39,75.56 v1(184.53,75.56) ; 185.47,72.26 185.47,71.83 185.55,71.75 185.55,70.94 ; v1(17.65,53.09) 17.22,52.65 14.81,52.65 14.61,52.45 14.61,50.67 14.35,50.42 14.35,49.86 ; v1(187.58,78.2) 185.77,80.01 181.74,80.01 181.28,79.55 181.28,78.18 181.31,78.16 181.31,77.42 ; 15.06,55.24 v1(16.13,55.24) ; v3(90.43,128.11) 90.58,127.96 90.58,127.68 90.18,127.29 90.18,126.58 ; v1(105.08,52.65) 105.71,52.65 105.99,52.37 105.99,51.82 ; 99.69,57.61 99.77,57.61 v1(100.2,58.04) ; 33.4,62.04 33.4,61.65 33.53,61.52 34.11,61.52 v1(34.42,61.21) ; 185.93,13.07 v1(185.93,13.84) ; v3(73.66,54.14) 73.81,54 73.81,53.74 73.61,53.54 73.41,53.54 ; 7.44,42.16 v1(8.64,42.16) ; 181.31,74.75 v1(181.31,75.69) ; 74.42,53.54 74.22,53.54 74.02,53.74 74.02,54 v3(74.17,54.14) ; v1(16.76,53.09) 12.4,53.09 12.22,52.91 12.22,52.45 11.24,52.45 10.16,53.53 ; 139.57,137.36 140.72,137.36 140.72,137.41 v1(140.08,138.05) ; 37.91,60.62 37.33,60.62 37.03,60.33 36.12,60.33 35.48,60.96 35.48,62.1 35.43,62.1 v1(34.92,62.61) ; 72.14,52.91 72.03,53.02 72.03,53.57 71.74,53.87 71.74,54.02 v3(71.88,54.17) ; 10.16,46.18 9.6,46.74 v1(8.38,46.74) ; 7.62,40.21 v1(8.64,40.21) ; 185.93,11.82 185.93,11.56 v1(186.44,11.05) ; 7.44,43.31 v1(8.38,43.31)
  TOP w0.203: 76.18,113.69 76.2,113.66 U8.19 ; v1(32,109.09) 32,108.97 32.1,108.87 U124.19
  TOP w0.254: U117.9 85.09,107.82 v1(84.96,107.7) ; U8.7 77.7,108.99 77.85,108.84 v1(77.85,108.58) ; 68.07,66.15 68.07,66.93 v1(67.94,67.06) ; v1(77.89,110.44) 78.08,110.63 U8.10 79.62,110.63 79.87,110.88 ; U3.9 80.64,84.2 v1(80.64,84.33) ; U2.6 66.68,85.97 v1(66.29,86.36) ; v1(75.76,114.74) 76.18,114.32 76.18,113.69 ; 79.87,110.88 79.62,110.88 79.38,111.13 U8.11 78.09,111.13 v1(77.89,111.33) ; 79.87,110.88 v1(79.87,110.87) ; U124.7 33.6,103.97 v1(34.05,103.52) ; 185.43,11.82 185.43,11.42 v1(185.8,11.05) ; v1(104.9,56.64) 104.78,56.77 104.22,56.77 103.96,56.52 ; v1(186.94,13.84) 186.43,13.33 186.43,13.07 ; 14.1,52.24 14.1,52.47 13.97,52.6 v1(13.46,52.6) ; 87.74,51.82 v1(88.52,51.82) 89.33,52.63 89.33,52.83 ; 92.72,120.47 v1(92.72,122.04) ; R104.2 81.66,107.11 81.66,108.33 81.92,108.58 ; Q14.4 71.37,112.15 v1(71.63,111.89) ; v1(92.72,116.2) 92.72,114.74
  TOP w0.305: U98.3 53.23,84.57 v1(53.47,84.33) ; U101.3 58.82,86.09 v1(58.8,86.11) ; 179.24,54.35 v1(179.96,54.35) ; v1(17.4,61.71) 16.58,61.71 ; v1(56.01,86.11) 56.02,86.09 U100.3
  TOP w0.381: v1(6.99,45.34) 7.14,45.5 7.87,45.5 ; v1(13.46,52.6) 13.31,52.45 12.92,52.45 ; v1(13.59,48.9) 13.05,48.9 12.92,49.02 ; v1(91.14,100.84) 91.24,100.84 91.36,100.97 R481.1 ; C403.2 57.96,79.6 v1(58.17,79.4) ; 183.95,69.09 v1(182.5,69.09) ; v1(58.67,82.68) 58.29,83.06 U104.2 ; 12.92,55.24 v1(13.46,55.24) ; v1(49.66,84.33) 49.78,84.45 U102.2 ; 9.02,45.26 8.69,45.26 v1(8.26,44.83) ; 5.33,37.62 v7(5.33,36.96) ; 12.92,54.1 v1(13.46,54.1) ; v1(32,60.14) 32.75,60.14 ; Q16.2 v1(76.82,136.02) ; U103.3 54.72,83.3 54.61,83.18 v1(54.61,82.68) ; 5.33,41.56 4.6,41.56 v1(4.32,41.27) ; 15.75,48.95 v1(16.38,48.95) ; v1(13.59,50.16) 12.92,50.16 12.92,50.9 13.16,51.13 13.16,51.31 ; 34.05,62.04 34.48,62.04 v1(34.67,61.85) ; R848.2 v1(56.03,77.88) ; v1(54.1,81.41) 54.74,80.77 C402.2 ; 29.96,60.14 v1(29.96,60.95)
  TOP w0.406: 179.66,51.31 v1(180.47,51.31)
  TOP w0.508: v1(65.15,80.64) 65.16,80.63 C60.2 ; 89.18,126.58 89.18,127.66 89.66,128.14 v1(89.92,128.14) ; R522.2 v1(53.47,84.33) ; 17.65,60.12 v1(17.25,59.59) ; 182.25,74.75 182.25,74.3 v1(181.74,73.79) ; v1(28.96,88.14) 28.69,88.4 27.69,88.4 ; v1(49.47,69.85) 48.51,69.85 48.18,69.52 R849.2 ; v1(183.26,62.53) 183.26,62.51 183.24,62.48 181.55,62.48 ; 78.84,100.84 C45.2 ; C45.2 78.84,102.62 ; C45.2 79.73,101.73 ; C45.2 77.95,101.73 ; 8.32,34.37 9.09,34.37 v1(9.27,34.54) ; v1(72.52,117.22) 73.23,117.22 C114.2 ; v1(24.51,100.58) 24.24,100.31 D54.1 ; C397.2 v1(53.21,88.77) ; v1(58.29,88.09) 58.75,88.54 C400.2 ; 41.1,70.36 41.1,71.24 v1(41.52,71.63) ; R658.2 83.31,107.07 v1(83.31,107.7) ; R68.2 68.45,67.82 68.58,67.69 v1(68.58,67.18) ; 22.86,65.74 22.17,65.74 v1(21.84,65.41) ; C424.2 R554.2 45.15,71.25 44.89,71.5 v1(44.58,71.5) ; 9.02,66.91 v1(9.02,65.79) ; v1(28.57,110.49) 29.2,110.49 C510.2 ; D51.1 23.62,92.96 23.22,93.37 v1(22.73,93.37) ; v1(4.19,37.29) 2.93,37.29 ; R118.2 v1(66.29,103.76) ; C419.2 v1(49.66,82.04) ; Q4.2 54.62,65.29 v1(54.86,65.53) ; C420.2 50.8,80.85 v1(50.8,81.41) ; v1(83.51,88.9) Q18.2 ; C110.2 v1(71.37,105.54) ; v1(33.15,100.46) 33.3,100.3 C509.1 ; v1(4.32,41.27) 4.11,41.07 2.93,41.07 ; R527.2 54.48,79.63 54.1,79.25 v1(54.1,78.87) ; 181.36,51.38 v1(182.12,51.38) ; C107.2 v1(79.88,108.08) ; v1(24,97.54) 24,97.03 24.24,96.79 D53.1 ; 181.55,61.21 v1(183.26,61.21) ; v1(58.17,71.98) 58.17,71.5 57.71,71.04 C416.2 ; 15.82,64.39 15.95,64.26 v1(16.89,64.26) ; v1(28.07,91.06) 28.19,91.19 28.75,91.19 ; 31.86,73.47 v1(31.86,75.18) ; v1(27.38,73.33) 27.38,73.3 27.52,73.16 28.19,73.16 ; v1(56.01,75.06) 56.72,75.06 R561.2 C418.1 ; C511.2 R687.1 31.62,101.22 v1(31.11,100.71) ; 9.02,57.17 v1(9.02,58.29) ; v1(75.44,116.33) 75.44,115.95 75.7,115.68 C112.2 75.7,114.8 v1(75.76,114.74) ; R57.2 80.34,85.27 v1(80.64,84.96) ; 186.39,72.26 v1(186.39,71.42) ; R524.2 50.29,82.6 v1(50.29,82.04) ; C399.2 v1(56.52,88.77) ; 184.66,76.5 v1(185.5,76.5) ; C422.2 45.21,78.66 45.21,78.75 44.84,79.12 44.75,79.12 44.73,79.15 43.9,79.15 C426.2 43.57,79.25 v1(42.9,79.25) ; 5.38,35.62 v1(4.38,35.62) ; 91.76,84.71 91.76,85.83 91.73,85.85 v1(91.68,85.85) ; v1(35.43,100.84) 35.81,101.22 C512.2 36.58,101.4 C513.2 ; 78.84,92.33 C44.2 ; C44.2 78.84,94.11 ; C44.2 77.95,93.22 ; C44.2 79.73,93.22 ; v1(37.1,62.78) 36.63,63.25 36.4,63.25 ; v1(85.6,113.28) 85.55,113.23 C477.2 ; 5.33,40.34 v1(4.45,40.34) ; 36.78,77.72 v1(36.78,78.49) ; R682.1 91.74,102.87 v1(91.14,102.87) ; 81.92,108.58 82.3,108.97 82.3,112.27 87.88,117.86 87.88,119.89 90.04,122.04 v1(92.72,122.04) ; R24.2 v1(58.55,63.37) ; v1(187.55,74.2) 187.83,73.91 187.83,73.42 187.06,73.42 186.94,73.53 186.39,73.53 ; Q15.2 66.94,105.93 66.8,105.79 v1(66.67,105.79) ; 182.19,78.87 v1(182.19,79.5) ; 35.31,82.47 v1(35.31,81.79) ; C414.2 57.07,68.71 58.04,68.71 58.8,69.47 v1(58.8,69.49) ; 2.93,43.52 v1(4.45,43.52) ; v1(32,109.09) v1(32,109.73) 32,109.86 32.33,110.19 C514.2 ; 91.18,133.77 91.18,134.87 v1(91.57,135.25) ; R556.2 42.27,73.84 v1(42.27,73.41) ; C423.2 v1(52.2,81.41) ; v1(63.75,103.25) 63.9,103.39 Q19.2 ; 16.27,65.66 v1(17.04,65.66) ; 182.25,77.42 182.25,76.96 v1(181.74,76.45) ; v1(80.52,105.66) 81.03,106.17 R104.2 ; 31.05,87.01 31.05,86.17 v1(30.86,85.98) ; v1(17.78,65.66) 17.78,64.47 17.65,64.34 ; v1(37.67,71.02) 38.44,70.25 38.54,70.25 ; v1(22.73,77.34) 22.99,77.09 D56.1 ; D55.1 v1(21.59,70.74) ; v1(44.58,76.56) 44.81,76.33 C421.2 ; R102.2 C104.1 74.17,106.17 v1(74.55,105.79) ; R697.2 37.8,103.62 v1(37.47,103.95) ; 92.18,126.58 v1(92.18,128.12) ; v1(88.9,90.42) 87.88,91.44 R114.2 ; 2.93,34.84 v1(4.27,34.84) ; v1(31.64,65.52) v1(33.91,65.52) ; 178.31,28.14 v1(178.31,28.83) ; v1(84.96,107.7) v1(84.33,107.7) 83.74,108.28 C476.1 ; v1(63.25,85.72) 63.3,85.67 C48.2 ; 181.55,58.67 v1(183.26,58.67) ; D59.1 v1(23.11,83.44) ; v1(46.86,80.84) 47.89,80.84 U108.2 ; D57.1 24.89,73.91 v1(25.4,73.41) ; D50.1 v1(23.11,86.61) ; 186.87,36.32 v1(186.06,36.32) ; D58.1 v1(22.73,80.26) ; 187.83,71.87 v1(187.83,70.99) ; 12.01,63.88 v1(12.01,66.24) ; v1(9.84,35.5) 9.72,35.62 9.03,35.62 ; v1(56.52,65.56) 55.87,66.21 Q3.2 ; C515.2 49.23,110.74 v1(47.75,110.74) ; v1(82.17,85.98) 81.97,86.18 C66.1 ; C516.2 v1(27.56,103) ; 5.33,44.27 v1(4.45,44.27) ; 181.55,59.94 v1(183.26,59.94) ; C105.1 v1(76.45,105.79) ; C401.2 v1(48.01,88.77) ; C82.1 v1(69.6,69.72) ; v1(69.98,90.81) C55.2 ; D52.1 v1(23.11,89.79) ; C497.1 v1(30.48,100.71) ; R693.2 v1(29.34,100.71) ; R91.1 v1(75.31,105.79) ; C425.2 v1(44.58,75.18) ; C108.2 v1(77.6,105.79)
  TOP w0.762: v1(40.13,58.93) 40.34,59.13 41.15,59.13
  L2-GND1 w0.254: 4.89,89.6 4.83,89.53 4.83,89.53 ; 184.21,106.04 184.91,106.04 184.91,106.05
  L2-GND1 w0.508: 78.84,100.84 C45.2 ; C45.2 77.95,101.73 ; C45.2 78.84,102.62 ; C45.2 79.73,101.73 ; C44.2 78.84,94.11 ; C44.2 78.84,92.33 ; C44.2 77.95,93.22 ; C44.2 79.73,93.22 ; 8.66,79.93 CN35.14 ; CN35.14 10.62,79.93 ; CN35.14 9.64,78.95 ; CN35.14 9.64,80.91 ; CN35.5 16.55,80.91 ; CN35.5 15.57,79.93 ; CN35.5 16.55,78.95 ; CN35.5 17.53,79.93 ; 59.18,72.91 CN19.4 ; CN19.4 60.06,73.79 ; CN19.4 58.31,73.79 ; CN19.4 59.18,74.66 ; 51.98,17.11 52.86,17.11 ; 8.89,53.53 8.06,53.53 ; 51.98,13.65 52.9,13.65 ; 50.98,11.92 50.14,11.92 ; 51.98,10.18 52.86,10.18
  L3-IN1 w0.089: v3(73.66,54.14) 73.81,54.29 73.81,54.38 v4(73.61,54.58) ; v4(71.93,54.61) 71.73,54.41 71.73,54.32 v3(71.88,54.17) ; v3(71.37,54.17) 71.53,54.32 71.53,54.41 v4(71.32,54.61) ; v3(74.17,54.14) 74.02,54.29 74.02,54.38 v4(74.22,54.58)
  L4-VCC1 w0.203: 184.78,112.01 184.34,112.01 184.21,112.14
  L4-VCC1 w0.254: 184.91,106.05 184.21,106.05 184.21,106.04
  L4-VCC1 w0.508: 8.66,79.93 CN35.14 ; CN35.14 10.62,79.93 ; CN35.14 9.64,80.91 ; CN35.14 9.64,78.95 ; CN35.5 16.55,80.91 ; CN35.5 17.53,79.93 ; CN35.5 15.57,79.93 ; CN35.5 16.55,78.95
  L5-VCC2 w0.508: 8.66,79.93 CN35.14 ; CN35.14 9.64,78.95 ; CN35.14 10.62,79.93 ; CN35.14 9.64,80.91 ; 51.98,17.11 52.74,17.11 ; 16.55,78.95 CN35.5 ; CN35.5 16.55,80.91 ; CN35.5 15.57,79.93 ; CN35.5 17.53,79.93 ; 50.98,11.92 50.19,11.92 ; 51.98,10.18 52.68,10.18 ; 51.98,13.65 52.64,13.65
  L6-IN2 w0.089: v1(8.38,46.74) 8.13,46.99 8.13,48.96 8.89,49.72 ; v1(8.38,43.31) 8.89,43.81 8.89,48.45 ; v1(8.64,40.21) 8.64,40.64 8.13,41.15 8.13,42.29 9.27,43.43 9.27,45.97 10.9,47.6 10.9,48.98 10.16,49.72
  L6-IN2 w0.508: v1(187.55,74.2) 187.13,73.79 v1(181.74,73.79)
  L7-GND2 w0.203: 184.21,112.14 184.34,112.01 184.78,112.01
  L7-GND2 w0.254: 184.21,106.04 184.91,106.04 184.91,106.05 ; 4.83,89.53 4.83,89.53 4.89,89.6
  L7-GND2 w0.508: 77.95,93.22 C44.2 ; C44.2 78.84,94.11 ; C44.2 78.84,92.33 ; C44.2 79.73,93.22 ; CN35.14 10.62,79.93 ; CN35.14 9.64,80.91 ; CN35.14 9.64,78.95 ; CN35.14 8.66,79.93 ; CN19.4 60.06,73.79 ; CN19.4 59.18,74.66 ; CN19.4 59.18,72.91 ; CN19.4 58.31,73.79 ; 15.57,79.93 CN35.5 ; CN35.5 16.55,78.95 ; CN35.5 17.53,79.93 ; CN35.5 16.55,80.91 ; 78.84,100.84 C45.2 ; C45.2 79.73,101.73 ; C45.2 78.84,102.62 ; C45.2 77.95,101.73 ; 8.89,53.53 8.06,53.53
  BOTTOM w0.089: 65.02,53.92 65.44,54.34 65.44,54.55 v6(65.33,54.66) ; v6(65.84,54.66) 65.75,54.58 65.75,54.34 66.17,53.92 ; 62.42,53.92 62.86,54.36 62.86,54.68 v6(62.75,54.79) ; v6(60.2,56.01) 60.31,55.9 60.31,54.34 59.89,53.92 ; v6(63.26,54.79) 63.18,54.71 63.18,54.31 63.56,53.92 ; v6(60.71,56.01) 60.62,55.92 60.62,54.34 61.04,53.92
  BOTTOM w0.102: 140.19,137.09 140.19,137.94 v1(140.08,138.05) ; 16.64,45.92 16.64,46.74 v1(15.88,47.5) ; 188.59,76.2 v1(187.71,76.2) ; 15.49,45.92 v1(15.49,46.61) ; 188.59,79.2 187.28,79.2 184.53,76.45 v1(184.53,75.56) ; 14.33,45.92 14.33,46.58 v1(15.24,47.5) ; 36.4,63.25 35.81,62.66 34.98,62.66 v1(34.92,62.61) ; 188.59,78.2 v1(187.58,78.2) ; v1(96.33,51.31) 97.16,52.13 97.16,52.76 98.73,52.76 99.69,53.72 104.01,53.72 v1(105.08,52.65) ; 35.48,62.1 35.48,60.96 34.67,60.96 v1(34.42,61.21) 34.14,61.49 33.5,61.49 33.4,61.59 33.4,62.04 ; 188.59,75.2 187.21,75.2 187.07,75.06 181.94,75.06 v1(181.31,75.69)
  BOTTOM w0.203: 91.05,62.91 91.05,63.25 90.81,63.5 v1(90.81,64.26) ; 90.05,65.61 90.05,65.01 90.2,64.87 v1(90.22,64.87)
  BOTTOM w0.254: 100.77,68.44 v1(99.96,68.44) ; v1(25.27,92.96) 25.02,93.21 23.68,93.21 ; 23.68,91.71 v1(22.73,91.71) ; R94.2 71.12,123.57 71.25,123.7 72.14,123.7 73.91,121.92 73.91,120.76 78.42,116.25 78.42,115.56 R815.2 ; v1(22.61,75.95) 22.88,76.22 23.68,76.22 ; 26.92,80.46 v1(26.92,81.41) ; 105.42,78.83 105.42,78.35 v1(105.79,77.98) ; 23.68,79.22 v1(22.73,79.22) ; 101.89,64.32 101.89,63.59 v1(101.98,63.5) ; 26.92,95.96 v1(26.92,96.91) ; 34.23,114.31 34.23,115.89 34.42,116.08 37.59,116.08 37.97,115.7 37.97,113.83 35.62,111.48 35.62,110.88 R513.1 ; v1(30.61,90.55) 30.44,90.71 29.66,90.71 ; v1(30.61,74.68) 30.06,75.22 29.66,75.22 ; 36.2,75.36 36.2,75.06 35.94,74.8 v1(35.43,74.8) ; 23.68,77.72 23.12,77.72 v1(22.73,78.11) ; 36.2,82.22 v1(36.2,81.28) ; v1(22.73,94.87) 22.89,94.71 23.68,94.71
  BOTTOM w0.305: C398.2 48.59,86.69 v1(48.13,86.23) ; U97.3 53.3,86.78 v1(53.98,86.11) ; U99.3 50.79,86.35 50.67,86.23 v1(50.29,86.23) ; v1(82.17,61.34) 82.63,60.88 82.63,60.76
  BOTTOM w0.381: 84.88,62.61 84.33,62.61 84.05,62.89 ; 84.05,62.89 83.85,62.69 83.19,62.69 ; 84.05,62.89 v1(84.05,62.92) ; 32.75,62.04 32.76,61.6 32.38,61.22 v1(32.13,61.21) ; 87.08,62.61 86.11,62.61 v1(85.72,62.99) ; U77.2 v1(95.15,75.82) ; v1(77.34,55.24) 77.51,55.42 78.23,55.42
  BOTTOM w0.508: v1(44.7,118.62) 44.7,119.08 R703.2 ; Q67.2 44.7,116.13 v1(44.7,116.84) ; 96.01,72.59 95.45,72.59 v1(95.25,72.39) ; Q41.2 90.44,68.98 v1(90.3,68.83) ; v1(92.15,78.94) 91.2,79.89 Q38.2 ; Q8.2 v1(46.99,87.76) ; Q40.2 v1(87.64,68.96) ; v1(30.61,98.81) 30.28,99.14 C457.2 ; v1(86.36,60.05) 86.66,59.74 87.12,59.74 ; 104.01,61.26 v1(104.67,61.26) ; 29.84,83.52 v1(29.84,84.2) ; 37.59,86.82 v1(38.4,86.82) ; 28.45,72.34 28.35,72.34 27.38,73.3 v1(27.38,73.33) ; v1(188.72,72.39) 188.59,72.53 188.59,73.2 ; C461.2 v1(25.27,100.58) ; v1(37.1,62.78) 37.07,62.78 36.4,62.1 ; 15.54,63.63 15.56,63.51 v1(15.56,62.93) ; Q17.2 v1(24.02,104.03) ; v1(44.7,121.41) 45.14,120.98 C504.1 ; v1(87.12,99.82) 88.14,99.82 C489.2 88.27,100.46 v1(87.12,100.46) ; C44.2 79.73,93.22 ; C44.2 78.84,92.33 ; C44.2 77.95,93.22 ; C44.2 78.84,94.11 ; v1(97.79,62.87) 97.59,63.07 97.59,64.01 ; 101.35,61.26 v1(102.08,61.26) ; 177.85,38.99 v1(177.85,38.2) ; C396.2 51.99,82.73 51.69,82.42 v1(51.69,82.04) ; 97.59,67.94 96.77,67.94 v1(96.65,68.07) ; 181.81,27.18 v1(182.63,27.18) ; v1(26.04,84.2) C475.2 C473.1 ; 184.48,28.45 184.48,27.18 184.66,27 v1(184.66,26.54) ; C45.2 79.73,101.73 ; C45.2 78.84,102.62 ; C45.2 78.84,100.84 ; C45.2 77.95,101.73 ; v1(92.96,60.83) 91.87,59.74 91.57,59.74 ; 188.59,74.2 v1(187.55,74.2) ; Q66.2 48.78,119.37 v1(48.26,119.89) ; v1(186.85,66.9) v1(183.9,66.9) ; 183.57,27.18 183.57,29.72 v1(182.88,29.72) ; C106.1 74.02,109.36 v1(75.09,110.44) ; v1(23.37,101.47) R457.1 22.73,100.08 v1(22.35,100.46) ; C454.1 28.27,99.14 v1(27.94,98.81) ; v1(85.09,66.04) 84.58,65.53 R503.2 ; v1(91.64,71.44) 91.64,72.57 90.3,73.91 C382.2 ; 38.18,79.5 v1(38.99,79.5) ; 183.57,32.26 v1(182.63,32.26) ; 28.32,87.71 28.52,87.71 v1(28.96,88.14) ; R113.2 v1(24.64,108.2) ; 179.45,28.14 v1(179.45,28.83) ; 95.33,65.53 v1(96.01,65.53) ; 16.51,60.69 v1(16.51,59.56) ; C125.2 v1(24.14,105.93) ; 178.31,28.14 v1(178.31,28.83)
  vias: v1(3.56,66.8) v1(3.56,63.5) v1(3.56,59.44) v1(3.56,56.13) v1(8.64,39.5) v1(10.92,56.9) v1(14.67,62.93) v1(14.67,61.15) v1(15.18,62.04) v1(15.56,61.15) v1(18.92,68.58) v1(18.92,67.94) v1(20.07,124.71) v1(20.07,123.95) v1(20.07,120.4) v1(20.07,118.11) v1(20.07,116.59) v1(20.32,105.79) v1(20.32,105.16) v1(20.32,104.52) v1(20.32,103.89) v1(20.57,49.15) v1(20.95,105.79) v1(20.95,105.16) v1(20.95,104.52) v1(20.95,103.89) v1(21.08,124.71) v1(21.08,123.95) v1(21.08,120.4) v1(21.08,115.32) v1(21.08,114.55) v1(21.08,113.79) v1(21.08,113.03) v1(21.08,109.73) v1(21.54,62.61) v1(21.59,118.11) v1(21.59,116.59) v1(21.84,63.17) v1(22.1,124.71) v1(22.1,123.95) v1(22.1,120.4) v1(22.1,115.32) v1(22.1,114.3) v1(22.1,113.03) v1(22.1,109.73) v1(22.17,62.61) v1(22.48,63.17) v1(22.81,62.61) v1(23.11,124.71) v1(23.11,123.95) v1(23.11,120.4) v1(23.11,118.11) v1(23.11,116.59) v1(23.11,115.32) v1(23.11,114.3) v1(23.11,113.03) v1(23.11,109.73) v1(23.11,63.17) v1(24.64,94.87) v1(24.77,91.06) v1(25.22,45.34) v1(25.27,79.5) v1(25.27,77.47) v1(25.27,75.41) v1(26.48,40.26) v1(26.67,94.87) v1(26.67,92.96) v1(26.67,91.06) v1(26.86,39.56) v1(27.05,79.5) v1(27.05,77.47) v1(27.05,75.41) v1(28.07,28.45) v1(28.57,94.87) v1(28.57,92.96) v1(28.7,79.5) v1(28.7,77.98) v1(28.7,75.41) v1(28.7,40.73) v1(28.7,28.42) v1(30.23,40.64) v1(30.48,28.45) v1(30.99,107.31) v1(30.99,106.3) v1(30.99,105.41) v1(31.62,49.28) v1(31.62,48.64) v1(31.62,47.75) v1(31.62,47.12) v1(31.88,116.08) v1(31.88,115.44) v1(31.88,114.81) v1(31.88,114.17) v1(31.88,51.44) v1(31.88,50.8) v1(31.88,50.16) v1(32,30.86) v1(32.35,106.35) v1(32.26,49.28) v1(32.26,48.64) v1(32.26,47.75) v1(32.26,47.12) v1(32.38,107.31) v1(32.38,105.41) v1(32.51,116.08) v1(32.51,51.44) v1(32.51,50.8) v1(32.51,50.16) v1(32.89,49.28) v1(32.89,48.64) v1(32.89,47.75) v1(32.89,47.12) v1(33.15,116.08) v1(33.78,116.08) v1(33.78,107.31) v1(33.78,106.3) v1(33.78,105.41) v1(33.78,35.94) v1(33.91,29.97) v1(34.8,28.57) v1(35.56,94.87) v1(35.56,94.11) v1(35.56,93.47) v1(35.69,39.75) v1(36.07,99.31) v1(36.07,98.68) v1(36.07,33.4) v1(36.45,94.87) v1(36.45,94.11) v1(36.45,93.47) v1(36.45,39.88) v1(36.58,115.44) v1(36.58,114.81) v1(36.58,114.17) v1(36.58,113.54) v1(36.7,99.31) v1(36.7,98.68) v1(36.7,33.4) v1(37.21,115.44) v1(37.21,114.81) v1(37.21,114.17) v1(37.34,99.31) v1(37.34,98.68) v1(37.34,33.4) v1(37.4,28.83) v1(37.47,94.87) v1(37.47,94.11) v1(37.47,93.47) v1(38.1,97.66) v1(38.1,96.9) v1(38.73,99.31) v1(38.73,98.68) v1(38.86,97.66) v1(38.86,96.9) v1(38.86,95.12) v1(38.86,94.49) v1(38.99,104.52) v1(38.99,103.89) v1(39.12,28.83) v1(39.37,99.31) v1(39.37,98.68) v1(39.5,97.66) v1(39.5,96.9) v1(39.5,95.12) v1(39.5,94.49) v1(40.01,99.31) v1(40.01,98.68) v1(40.13,97.66) v1(40.13,96.9) v1(40.13,95.12) v1(40.13,94.49) v1(40.51,65.91) v1(40.51,65.28) v1(40.77,106.93) v1(40.77,106.3) v1(40.77,104.52) v1(40.77,103.89) v1(41.15,65.91) v1(41.15,65.28) v1(41.27,42.55) v1(41.53,33.66) v1(41.78,66.55) v1(41.78,65.91) v1(41.78,65.28) v1(42.42,66.55) v1(42.42,65.91) v1(42.42,65.28) v1(42.93,27.18) v1(43.05,65.28) v1(43.69,42.93) v1(43.81,27.15) v1(44.07,26.54) v1(44.2,40.51) v1(44.2,39.88) v1(44.2,39.12) v1(44.96,26.42) v1(45.72,110.74) v1(45.68,23.5) v1(45.97,107.19) v1(45.97,105.54) v1(45.97,103.76) v1(45.97,66.55) v1(45.97,65.91) v1(45.97,65.28) v1(46.23,110.11) v1(46.23,109.22) v1(46.23,108.33) v1(46.48,104.65) v1(46.61,107.19) v1(46.61,105.54) v1(46.61,103.76) v1(46.61,66.55) v1(46.61,65.91) v1(46.61,65.28) v1(46.74,29.97) v1(46.99,118.36) v1(46.99,117.73) v1(46.99,117.09) v1(46.99,110.11) v1(46.99,109.22) v1(46.99,108.33) v1(47.1,37.95) v1(47.24,107.19) v1(47.24,105.54) v1(47.24,103.76) v1(47.24,65.91) v1(47.24,65.28) v1(47.24,30.35) v1(47.62,25.78) v1(47.62,25.15) v1(48.51,30.48) v1(49.15,29.84) v1(49.53,76.2) v1(49.53,74.93) v1(49.53,73.66) v1(49.53,72.39) v1(49.62,26.12) v1(49.62,23.53) v1(49.66,30.48) v1(49.78,118.87) v1(49.78,118.24) v1(49.78,117.6) v1(49.78,116.97) v1(50.42,118.87) v1(50.8,76.2) v1(50.8,74.93) v1(50.8,73.66) v1(50.8,72.39) v1(51.05,110.74) v1(51.05,110.11) v1(51.05,40.39) v1(51.05,30.48) v1(51.18,29.84) v1(51.56,28.07) v1(51.56,27.43) v1(51.69,110.74) v1(51.69,110.11) v1(52.07,118.87) v1(52.07,76.2) v1(52.07,74.93) v1(52.07,73.66) v1(52.07,72.39) v1(52.07,49.28) v1(52.07,48.64) v1(52.07,48.01) v1(52.07,47.37) v1(52.07,46.74) v1(52.2,40.39) v1(52.2,28.07) v1(52.32,35.94) v1(52.32,30.48) v1(52.32,29.84) v1(52.7,118.87) v1(52.7,49.28) v1(52.7,48.64) v1(52.7,48.01) v1(52.7,47.37) v1(52.96,35.94) v1(53.34,76.2) v1(53.34,74.93) v1(53.34,73.66) v1(53.34,72.39) v1(53.34,49.28) v1(53.34,48.64) v1(53.34,48.01) v1(53.34,47.37) v1(53.34,40.39) v1(53.72,30.48) v1(53.72,29.84) v1(53.85,26.04) v1(53.85,23.75) v1(53.98,110.74) v1(53.98,110.11) v1(53.98,49.28) v1(53.98,48.64) v1(53.98,48.01) v1(53.98,47.37) v1(54.23,41.48) v1(54.23,40.26) v1(54.46,29.84) v1(54.61,49.28) v1(54.61,48.64) v1(54.61,48.01) v1(54.61,47.37) v1(54.86,30.48) v1(55.37,25.68) v1(55.5,53.47) v1(55.5,52.7) v1(55.5,51.69) v1(55.5,50.55) v1(55.5,49.28) v1(55.63,118.87) v1(55.63,118.24) v1(55.63,117.35) v1(55.63,116.71) v1(55.87,23.91) v1(56.01,28.07) v1(56.13,30.48) v1(56.13,29.84) v1(56.16,36.96) v1(56.26,39.24) v1(56.39,42.67) v1(56.54,23.9) v1(57.05,56.77) v1(57,45.21) v1(57.25,52.2) v1(57.25,42.67) v1(57.37,32.71) v1(57.4,23.88) v1(57.91,21.59) v1(58.04,23.88) v1(58.42,118.87) v1(58.42,118.24) v1(58.42,48.07) v1(58.42,47.43) v1(58.42,33.02) v1(58.55,22.1) v1(58.55,21.46) v1(58.8,56.77) v1(58.8,22.73) v1(58.93,39.62) v1(59.04,23.88) v1(59.05,118.87) v1(59.18,22.1) v1(59.18,21.46) v1(59.31,33.02) v1(59.44,42.65) v1(59.44,22.73) v1(59.56,24.56) v1(59.69,93.73) v1(59.69,93.09) v1(59.69,92.46) v1(59.72,55.8) v1(59.69,28.83) v1(59.69,19.68) v1(59.82,48.12) v1(59.82,47.49) v1(59.82,35.43) v1(59.91,50.19) v1(60.2,127.51) v1(60.33,124.21) v1(60.33,123.57) v1(60.33,122.94) v1(60.33,121.79) v1(60.33,121.16) v1(60.33,120.52) v1(60.33,93.73) v1(60.33,93.09) v1(60.33,92.46) v1(60.73,37.34) v1(60.83,23.11) v1(60.96,124.21) v1(60.96,123.57) v1(60.96,122.94) v1(60.96,121.79) v1(60.96,121.16) v1(60.96,120.52) v1(60.96,93.73) v1(60.96,93.09) v1(60.96,92.46) v1(60.96,42.67) v1(61.09,28.7) v1(61.21,55.83) v1(61.34,48.04) v1(61.34,47.41) v1(61.34,45.21) v1(61.34,26.8) v1(61.47,19.18) v1(61.59,93.73) v1(61.59,93.09) v1(61.98,52.07) v1(62.23,93.73) v1(62.23,93.09) v1(62.18,54.61) v1(62.64,32.13) v1(62.74,33.86) v1(62.87,48.04) v1(62.87,47.41) v1(62.99,62.48) v1(62.99,61.85) v1(62.99,50.06) v1(63.02,25.02) v1(62.99,22.23) v1(63.17,18.8) v1(63.27,32.13) v1(63.63,62.48) v1(63.63,61.85) v1(63.88,54.74) v1(64.01,32.13) v1(64.26,52.2) v1(64.39,48.04) v1(64.39,47.41) v1(64.64,21.21) v1(64.77,54.61) v1(64.9,114.17) v1(64.9,107.82) v1(64.9,107.19) v1(64.9,63.12) v1(64.9,62.48) v1(64.9,61.85) v1(65.15,39.12) v1(65.28,21.21) v1(65.53,114.17) v1(65.53,107.82) v1(65.53,107.19) v1(65.53,63.12) v1(65.53,62.48) v1(65.53,61.85) v1(65.51,59.79) v1(65.48,26.64) v1(65.66,37.47) v1(65.79,38.1) v1(65.91,21.21) v1(66.17,114.17) v1(66.27,59.79) v1(66.27,50.95) v1(66.42,54.61) v1(66.42,38.99) v1(66.42,38.1) v1(66.67,63.12) v1(66.67,62.48) v1(66.67,61.85) v1(66.93,79.5) v1(66.93,78.87) v1(66.93,59.79) v1(67.06,114.17) v1(67.18,112.27) v1(67.18,111.63) v1(67.18,111) v1(67.18,110.36) v1(67.18,28.96) v1(67.18,27.81) v1(67.31,63.12) v1(67.31,62.48) v1(67.31,61.85) v1(67.44,23.04) v1(67.56,19.94) v1(67.69,114.17) v1(67.82,112.27) v1(67.82,111.63) v1(67.82,111) v1(67.82,110.36) v1(67.94,63.12) v1(68.07,33.78) v1(68.07,32.26) v1(68.2,45.21) v1(68.2,43.05) v1(68.2,41.66) v1(68.33,114.17) v1(68.45,112.27) v1(68.45,111.63) v1(68.45,111) v1(68.45,110.36) v1(69.34,39.75) v1(69.34,38.73) v1(69.26,35.69) v1(69.47,92.71) v1(69.47,92.08) v1(69.6,25.15) v1(69.85,22.07) v1(69.85,20.19) v1(69.98,44.7) v1(69.98,43.56) v1(69.98,42.67) v1(69.98,41.53) v1(69.98,40.64) v1(70.1,51.18) v1(70.48,32.64) v1(70.48,32) v1(70.74,121.54) v1(70.74,120.9) v1(70.74,39.75) v1(70.74,38.73) v1(70.82,54.33) v1(71.12,42.67) v1(71.12,41.53) v1(71.12,40.64) v1(71.37,121.54) v1(71.37,120.9) v1(71.5,26.16) v1(71.63,62.99) v1(71.63,62.36) v1(71.63,35.94) v1(71.63,32) v1(71.75,92.46) v1(71.75,91.82) v1(71.75,45.97) v1(71.88,44.32) v1(71.88,28.45) v1(72.01,90.3) v1(72.01,43.05) v1(72.01,41.78) v1(72.01,22.23) v1(72.01,19.3) v1(72.26,62.99) v1(72.26,62.36) v1(72.26,39.75) v1(72.26,38.73) v1(72.39,92.46) v1(72.39,91.82) v1(72.44,54.36) v1(72.64,90.3) v1(72.77,48.51) v1(72.9,62.99) v1(72.9,62.36) v1(73.03,92.46) v1(73.03,91.82) v1(73.03,44.32) v1(73.08,54.36) v1(73.15,43.05) v1(73.15,41.78) v1(73.66,91.31) v1(73.66,62.99) v1(73.66,62.36) v1(73.66,31.75) v1(73.79,39.75) v1(73.79,38.73) v1(74.04,41.02) v1(74.04,22.1) v1(74.04,20.24) v1(74.17,45.09) v1(74.17,43.94) v1(74.17,42.67) v1(74.3,62.99) v1(74.3,62.36) v1(74.3,31.75) v1(74.42,26.67) v1(74.55,90.81) v1(74.75,54.36) v1(75.09,112.35) v1(75.09,111.33) v1(75.18,32.89) v1(75.31,41.02) v1(75.44,138.18) v1(75.44,45.09) v1(75.44,43.94) v1(75.44,42.67) v1(75.44,39.88) v1(75.44,38.73) v1(75.56,81.66) v1(75.56,79.63) v1(75.56,78.99) v1(75.64,46.02) v1(75.74,35.05) v1(75.82,26.16) v1(75.95,27.43) v1(76.2,81.66) v1(76.2,79.63) v1(76.2,78.99) v1(76.2,77.47) v1(76.2,28.96) v1(76.18,22.36) v1(76.18,19.56) v1(76.33,90.93) v1(76.33,90.3) v1(76.33,78.11) v1(76.37,35.27) v1(76.49,112.35) v1(76.45,111.38) v1(76.48,110.44) v1(76.83,137.92) v1(77.09,77.47) v1(77.09,36.63) v1(77.34,90.93) v1(77.34,90.3) v1(77.34,79.63) v1(77.34,78.99) v1(77.47,112.33) v1(77.72,93.22) v1(77.85,97.79) v1(77.85,96.77) v1(77.85,95.76) v1(77.85,94.61) v1(77.98,102.87) v1(77.98,100.08) v1(77.98,79.63) v1(77.98,78.99) v1(77.98,34.19) v1(77.98,33.27) v1(78.11,78.11) v1(78.11,21.46) v1(78.38,43.46) v1(78.36,27.81) v1(78.36,20.45) v1(78.49,90.93) v1(78.49,90.3) v1(78.61,44.07) v1(78.74,99.06) v1(78.74,97.79) v1(78.74,96.77) v1(78.74,95.76) v1(78.68,77.41) v1(78.74,46.74) v1(78.74,42.93) v1(78.87,94.61) v1(78.87,91.82) v1(78.87,79.63) v1(78.87,78.99) v1(78.87,45.57) v1(79.5,102.87) v1(79.5,90.93) v1(79.5,90.3) v1(79.63,100.08) v1(79.63,97.79) v1(79.63,96.77) v1(79.63,95.76) v1(79.63,78.11) v1(79.76,79.63) v1(79.76,78.99) v1(79.95,77.41) v1(79.88,31.5) v1(80.14,32.47) v1(80.14,20.21) v1(80.39,80.77) v1(80.64,38.23) v1(81.03,137.54) v1(81.03,136.91) v1(81.03,78.99) v1(81.03,78.36) v1(81.09,77.41) v1(81.08,45.21) v1(81.11,42.52) v1(81.53,54.9) v1(81.66,137.54) v1(81.66,136.91) v1(81.66,37.08) v1(82.04,20.07) v1(82.01,18) v1(82.17,54.9) v1(82.3,137.54) v1(82.3,136.91) v1(82.42,34.23) v1(82.42,33.27) v1(82.68,17.96) v1(82.8,56.67) v1(82.8,54.9) v1(83.31,137.54) v1(83.31,136.91) v1(83.44,56.67) v1(83.44,54.9) v1(83.38,53.26) v1(83.44,47.75) v1(83.44,47.12) v1(83.44,45.34) v1(83.5,40.83) v1(83.57,22.35) v1(83.69,52.7) v1(83.82,126.49) v1(83.82,125.86) v1(83.82,124.84) v1(83.82,124.21) v1(83.95,137.54) v1(83.95,136.91) v1(84.01,53.26) v1(84.07,47.75) v1(84.07,47.12) v1(84.07,45.34) v1(84.07,20.13) v1(84.33,52.7) v1(84.33,43.18) v1(84.33,42.55) v1(84.65,53.26) v1(84.77,50.99) v1(84.96,137.54) v1(84.96,136.91) v1(84.96,52.7) v1(84.96,43.18) v1(84.96,42.55) v1(85.72,32.89) v1(86.11,19.7) v1(86.23,22.99) v1(87.38,123.06) v1(87.35,122.43) v1(87.69,20.13) v1(87.76,34.42) v1(87.88,17.98) v1(88.01,29.46) v1(88.5,131.44) v1(88.52,122.3) v1(88.77,107.7) v1(88.77,107.06) v1(88.77,106.43) v1(89.15,132.08) v1(89.15,131.44) v1(89.41,107.7) v1(89.41,107.06) v1(89.41,106.43) v1(89.37,24.68) v1(89.53,82.8) v1(89.53,81.66) v1(89.53,79.76) v1(89.53,79.12) v1(89.53,18.16) v1(89.66,84.66) v1(89.92,51.05) v1(89.92,21.65) v1(90.2,63.63) v1(90.17,28.32) v1(90.3,18.16) v1(90.55,132.21) v1(90.55,130.81) v1(90.81,56.52) v1(90.93,58.04) v1(91.44,64.87) v1(91.44,63.63) v1(91.47,128.12) v1(91.82,29.84) v1(91.82,18.16) v1(91.95,25.15) v1(92.33,45.85) v1(92.33,45.21) v1(92.33,44.58) v1(92.33,42.93) v1(92.46,22.1) v1(92.58,32.64) v1(92.58,31.11) v1(92.58,30.48) v1(92.58,29.84) v1(92.84,124.59) v1(92.96,45.85) v1(92.96,45.21) v1(92.96,44.58) v1(92.96,42.93) v1(93.83,102) v1(93.85,135.64) v1(93.89,128.12) v1(93.98,105.16) v1(93.98,103.89) v1(93.97,90.56) v1(94.03,85.85) v1(94.11,53.34) v1(94.23,58.42) v1(94.23,52.7) v1(94.36,111.38) v1(94.49,55.63) v1(94.49,54.99) v1(94.49,21.34) v1(94.49,20.07) v1(94.69,101.99) v1(94.74,53.34) v1(94.83,93.51) v1(94.87,90.55) v1(94.87,52.7) v1(95.12,55.63) v1(95.12,54.99) v1(95.25,135.64) v1(95.22,31.37) v1(95.38,53.34) v1(95.5,128.14) v1(95.5,21.34) v1(95.63,56.26) v1(96.01,105.28) v1(96.01,56.9) v1(96.01,53.34) v1(96.14,124.33) v1(96.42,93.45) v1(96.39,21.34) v1(96.52,101.98) v1(96.46,92.04) v1(96.61,103.59) v1(96.72,121.99) v1(96.72,116.4) v1(96.77,122.68) v1(96.77,88.65) v1(96.9,82.93) v1(96.9,80.39) v1(96.95,79.63) v1(97.16,124.97) v1(97.28,35.05) v1(97.28,21.34) v1(97.39,104.99) v1(97.41,92.08) v1(97.54,99.09) v1(97.54,93.52) v1(97.56,96.55) v1(97.65,105.58) v1(97.66,86.61) v1(97.66,85.98) v1(97.92,128.14) v1(98.04,131.32) v1(98.18,135.38) v1(98.21,94.98) v1(98.17,91.95) v1(98.31,101.99) v1(98.3,96.01) v1(98.3,32.51) v1(98.3,18.54) v1(98.39,35.84) v1(98.52,103.48) v1(98.5,102.62) v1(98.55,20.32) v1(98.81,131.32) v1(98.81,30.86) v1(98.81,21.34) v1(99.06,135.38) v1(99.2,102) v1(99.19,92.08) v1(99.39,100.48) v1(99.4,96.61) v1(99.44,93.6) v1(99.5,128.27) v1(99.95,122.17) v1(99.92,94.9) v1(99.89,52.45) v1(100.08,30.86) v1(100.08,20.32) v1(100.33,105.41) v1(100.33,52.96) v1(100.46,44.32) v1(100.46,43.69) v1(100.46,43.05) v1(100.71,30.86) v1(100.84,100.71) v1(100.93,92.06) v1(100.97,99.01) v1(101.09,44.32) v1(101.09,37.59) v1(101.09,36.96) v1(101.22,93.6) v1(101.16,34.67) v1(101.35,30.86) v1(101.47,122.05) v1(101.6,128.27) v1(101.6,69.98) v1(101.66,103.81) v1(101.73,68.45) v1(101.78,135.97) v1(101.91,98.99) v1(101.85,66.93) v1(101.98,123.32) v1(101.98,65.41) v1(102.08,100.71) v1(102.18,135.18) v1(102.23,131.19) v1(102.36,116.33) v1(102.41,37.85) v1(102.43,35.81) v1(102.36,34.1) v1(102.51,36.83) v1(102.74,118.49) v1(102.73,95.01) v1(102.79,96.39) v1(102.87,131.19) v1(102.87,125.09) v1(102.87,84.33) v1(102.87,82.42) v1(103,100.71) v1(103,28.32) v1(103.12,47.5) v1(103.12,46.74) v1(103.18,135.15) v1(103.25,128.27) v1(103.25,69.98) v1(103.38,123.32) v1(103.38,68.45) v1(103.5,135.99) v1(103.5,131.19) v1(103.5,125.09) v1(103.5,66.93) v1(103.5,65.41) v1(103.63,94.87) v1(103.63,28.32) v1(103.68,96.31) v1(103.76,100.71) v1(103.77,99.05) v1(103.91,91.46) v1(103.91,90.6) v1(103.89,48.26) v1(103.89,46.74) v1(104.01,103.76) v1(103.99,89.92) v1(104.14,125.09) v1(104.14,107.06) v1(104.09,102.23) v1(104.22,118.57) v1(104.19,116.33) v1(104.43,96.33) v1(104.39,26.92) v1(104.52,128.27) v1(104.72,102.13) v1(104.78,48.26) v1(104.78,46.74) v1(104.9,69.98) v1(105.03,122.56) v1(105.03,68.45) v1(105.03,66.93) v1(105.03,65.41) v1(105.16,30.86) v1(105.16,29.72) v1(105.16,28.45) v1(105.16,24.64) v1(105.36,116.33) v1(105.54,125.09) v1(105.54,34.04) v1(105.54,33.4) v1(105.54,31.37) v1(105.54,30.23) v1(105.54,20.32) v1(105.54,18.54) v1(105.66,128.27) v1(105.66,48.26) v1(105.66,46.74) v1(105.79,118.49) v1(105.79,113.16) v1(106.18,135.37) v1(106.17,27.94) v1(106.3,122.56) v1(106.3,24.64) v1(106.43,16) v1(106.55,69.98) v1(106.55,68.45) v1(106.55,66.93) v1(106.55,65.41) v1(106.68,103.9) v1(106.68,44.07) v1(106.68,18.54) v1(106.81,21.72) v1(106.89,63.55) v1(106.93,29.84) v1(107.06,54.74) v1(107.18,135.25) v1(107.31,24.64) v1(107.31,22.99) v1(107.44,38.38) v1(107.54,81.43) v1(107.7,125.04) v1(107.7,14.61) v1(107.76,85.1) v1(107.77,38.99) v1(107.82,28.07) v1(107.95,18.54) v1(108.33,128.02) v1(108.39,113.98) v1(108.52,65.21) v1(108.58,107.31) v1(108.71,52.7) v1(108.84,25.46) v1(108.84,24.83) v1(108.84,22.1) v1(108.97,16) v1(109.28,73.72) v1(109.54,113.98) v1(109.73,56.36) v1(109.91,30.86) v1(109.86,29.59) v1(109.86,28.96) v1(109.98,14.61) v1(110.18,135.33) v1(110.24,46.23) v1(110.36,132.33) v1(110.62,107.7) v1(110.62,81.53) v1(110.62,25.27) v1(110.62,24.64) v1(110.62,22.99) v1(110.55,21.72) v1(110.62,18.41) v1(110.74,128.27) v1(110.74,47.37) v1(110.93,44.07) v1(111,131.19) v1(111,124.16) v1(111,16) v1(111.06,42.35) v1(111.18,135.19) v1(111.24,49.78) v1(111.25,52.45) v1(111.38,128.27) v1(111.63,131.19) v1(111.76,55.88) v1(111.76,53.34) v1(111.89,49.78) v1(111.91,45.34) v1(112.01,14.61) v1(112.27,30.86) v1(112.27,30.23) v1(112.39,24.83) v1(112.39,22.1) v1(112.78,16) v1(113.11,118.8) v1(113.16,59.56) v1(113.16,28.32) v1(113.41,48.51) v1(113.41,37.97) v1(113.41,29.59) v1(113.41,28.96) v1(113.41,18.67) v1(113.67,131.44) v1(113.67,125.09) v1(113.67,116.46) v1(113.78,51.69) v1(113.92,89.79) v1(113.92,81.66) v1(113.92,58.67) v1(113.92,24.64) v1(114.05,33.15) v1(114.05,29.59) v1(114.05,28.96) v1(114.05,22.99) v1(114.18,135.27) v1(114.3,131.32) v1(114.3,21.72) v1(114.43,57.66) v1(114.55,46.04) v1(114.55,16) v1(114.72,122.05) v1(114.68,39.24) v1(114.81,24.64) v1(115.06,89.53) v1(115.18,135.25) v1(115.19,61.77) v1(115.19,57.66) v1(115.32,116.46) v1(115.32,79.2) v1(115.32,58.93) v1(115.25,43.94) v1(115.57,55.88) v1(115.57,53.34) v1(115.7,31.75) v1(115.7,28.96) v1(115.7,24.64) v1(115.7,18.67) v1(115.82,72.52) v1(115.82,22.99) v1(115.82,21.72) v1(115.95,79.2) v1(115.95,47.12) v1(116.18,125.12) v1(116.2,122.05) v1(116.33,123.83) v1(116.59,91.69) v1(116.59,58.93) v1(116.59,57.66) v1(116.59,47.12) v1(116.84,128.52) v1(116.84,125.09) v1(116.78,117.03) v1(117.35,63.93) v1(117.35,43.94) v1(117.47,117.03) v1(117.47,94.74) v1(117.6,31.11) v1(117.73,125.09) v1(117.84,118.88) v1(117.86,44.45) v1(117.98,25.65) v1(118.18,135.33) v1(118.49,37.08) v1(118.62,81.15) v1(118.64,74.42) v1(119.02,78.51) v1(119,64.77) v1(119.18,135.32) v1(119.22,118.75) v1(119.22,116.62) v1(119.38,58.42) v1(119.38,55.88) v1(119.46,73.41) v1(119.51,48.26) v1(119.51,46.74) v1(119.76,30.61) v1(120.02,61.72) v1(120.14,127.95) v1(120.09,73.36) v1(120.4,86.11) v1(120.45,38.58) v1(120.52,116.59) v1(120.72,118.87) v1(120.73,73.33) v1(120.78,132.33) v1(120.78,48.26) v1(120.78,46.74) v1(121.16,86.11) v1(121.54,37.47) v1(121.92,48.26) v1(121.92,46.74) v1(122.18,132.32) v1(122.18,127.89) v1(122.17,118.87) v1(122.24,116.27) v1(122.17,22.1) v1(122.3,93.34) v1(122.36,52.77) v1(122.81,23.5) v1(122.81,22.86) v1(123.06,132.33) v1(123.06,124.59) v1(123.19,128.02) v1(123.19,85.98) v1(123.32,135.25) v1(123.44,84.52) v1(123.44,75.31) v1(123.44,53.98) v1(123.44,41.15) v1(123.44,23.5) v1(123.44,22.86) v1(123.55,91.96) v1(123.7,97.66) v1(123.98,113.13) v1(124.03,57.81) v1(124.08,42.93) v1(124.08,41.15) v1(124.23,124.59) v1(124.21,116.27) v1(124.44,23.51) v1(124.46,80.52) v1(124.59,53.72) v1(124.71,132.33) v1(124.7,57.89) v1(124.69,55.75) v1(124.71,47.88) v1(124.71,47.24) v1(124.84,116.27) v1(124.97,135.25) v1(124.97,43.31) v1(124.97,42.67) v1(124.97,41.78) v1(124.97,41.15) v1(124.97,40.13) v1(125.18,128.02) v1(125.22,118.85) v1(125.73,40.13) v1(125.91,29.16) v1(126.18,128.07) v1(126.36,118.24) v1(126.49,48.26) v1(126.49,46.74) v1(126.75,54.86) v1(126.94,82.93) v1(127,56.9) v1(127.13,125.09) v1(127.13,80.52) v1(127.13,53.64) v1(127.18,132.26) v1(127.25,135.25) v1(127.38,93.09) v1(127.51,87) v1(127.69,87.96) v1(127.71,67.46) v1(127.76,48.26) v1(127.76,46.74) v1(127.99,71.91) v1(128.02,30.48) v1(128.02,29.34) v1(128.02,28.19) v1(128.14,61.85) v1(128.14,34.04) v1(128.14,32.89) v1(128.14,31.62) v1(128.35,124.89) v1(128.32,71.27) v1(128.35,67.46) v1(128.4,59.69) v1(128.4,56.39) v1(128.5,95.78) v1(128.65,132.33) v1(128.65,113.92) v1(128.78,117.47) v1(128.91,135.18) v1(128.91,52.96) v1(128.91,20.95) v1(129.03,88.52) v1(129.03,48.26) v1(129.03,46.74) v1(129.03,23.37) v1(129.34,82.44) v1(129.29,80.01) v1(129.41,128.02) v1(129.41,125.09) v1(129.95,80.3) v1(129.92,53.72) v1(129.97,82.44) v1(130.05,56.52) v1(130.18,121.41) v1(130.43,122.68) v1(130.43,122.05) v1(130.35,119.76) v1(130.37,83.82) v1(130.43,75.18) v1(130.43,74.55) v1(130.53,34.04) v1(130.53,32.89) v1(130.53,31.62) v1(130.53,30.48) v1(130.53,29.34) v1(130.53,28.19) v1(130.56,72.39) v1(130.56,64.39) v1(130.68,86.36) v1(130.92,125.17) v1(130.87,71.37) v1(130.87,70.74) v1(131.06,74.55) v1(131.06,73.69) v1(131.06,40.13) v1(131.18,135.13) v1(131.19,55.31) v1(131.57,81.28) v1(131.57,79.93) v1(131.65,57.89) v1(131.57,43.13) v1(131.55,21.95) v1(131.7,40.13) v1(131.7,38.99) v1(131.95,132.33) v1(131.95,118.64) v1(132.02,70.93) v1(132.02,54.04) v1(132.08,82.63) v1(132.21,120.14) v1(132.21,112.78) v1(132.21,89.66) v1(132.46,125.15) v1(132.46,86.36) v1(132.59,115.06) v1(132.59,74.42) v1(132.72,115.7) v1(132.72,113.28) v1(132.84,135.25) v1(132.84,89.66) v1(132.84,41.02) v1(132.84,40.39) v1(132.89,57.91) v1(133.1,82.55) v1(133.1,79.93) v1(133.22,115.06) v1(133.35,115.7) v1(133.45,64.39) v1(133.6,47.37) v1(133.86,43.18) v1(133.86,42.55) v1(134.11,23.27) v1(134.11,20.83) v1(134.19,125.17) v1(134.24,65.02) v1(134.24,47.37) v1(134.3,123.57) v1(134.49,43.18) v1(134.49,42.55) v1(134.49,40.89) v1(134.49,40.26) v1(134.62,82.55) v1(134.62,81.31) v1(134.62,79.93) v1(134.75,135.25) v1(135.25,132.33) v1(135.25,28.07) v1(135.42,123.61) v1(135.51,40.64) v1(135.51,40.01) v1(135.89,59.82) v1(135.89,22.99) v1(136.04,69.41) v1(136.14,94.87) v1(136.14,66.47) v1(136.14,53.72) v1(136.27,82.3) v1(136.27,74.42) v1(136.27,48.26) v1(136.27,46.74) v1(136.65,132.33) v1(136.65,56.39) v1(136.84,66.5) v1(136.91,135.2) v1(136.91,76.56) v1(137.18,125.09) v1(137.16,55.7) v1(137.5,69.41) v1(137.54,63.63) v1(137.54,48.26) v1(137.54,46.74) v1(137.79,34.29) v1(137.79,33.27) v1(137.79,31.75) v1(137.79,30.25) v1(137.79,29.62) v1(137.97,29.01) v1(138.56,97.16) v1(138.56,75.69) v1(138.68,38.61) v1(138.81,58.42) v1(138.81,48.26) v1(138.81,46.74) v1(138.94,57.02) v1(139,123.32) v1(139.18,135.37) v1(139.18,132.34) v1(139.33,76.07) v1(139.32,33.91) v1(139.32,32.26) v1(139.32,30.61) v1(139.32,28.98) v1(139.45,58.42) v1(139.57,83.82) v1(139.57,79.96) v1(139.91,131.24) v1(140.14,123.32) v1(140.08,24.64) v1(140.18,125.12) v1(140.21,78.99) v1(140.21,39.62) v1(140.34,37.34) v1(140.46,34.92) v1(140.54,28.98) v1(140.62,43.72) v1(140.72,76.83) v1(140.72,62.23) v1(140.72,24.64) v1(141.16,65.09) v1(141.22,22.48) v1(141.35,24.64) v1(141.48,71.63) v1(141.48,68.17) v1(141.6,79.12) v1(141.6,37.34) v1(141.73,28.96) v1(141.67,24.07) v1(141.86,109.09) v1(141.86,93.15) v1(141.85,59.38) v1(141.86,22.48) v1(141.99,138.05) v1(141.99,115.7) v1(141.99,115.06) v1(141.99,42.16) v1(141.99,33.91) v1(141.99,32.26) v1(141.99,30.61) v1(142.11,71.63) v1(142.11,54.29) v1(142.43,94.46) v1(142.37,34.92) v1(142.62,61.85) v1(142.56,22.48) v1(142.68,78.17) v1(142.88,82.17) v1(142.98,135.18) v1(143,132.33) v1(143,123.32) v1(143.13,68.17) v1(143.18,125.24) v1(143.19,22.48) v1(143.32,107.12) v1(143.26,61.85) v1(143.26,28.83) v1(143.38,42.16) v1(143.51,89.6) v1(143.51,76.07) v1(143.57,94.93) v1(143.57,75.37) v1(143.57,66.04) v1(143.64,34.92) v1(143.76,48.39) v1(143.76,34.04) v1(143.76,33.02) v1(143.76,31.88) v1(143.76,30.73) v1(143.76,29.46) v1(144.15,123.32) v1(144.18,125.21) v1(144.4,78.61) v1(144.4,77.98) v1(144.4,77.34) v1(144.78,100.71) v1(144.78,96.27) v1(144.78,52.45) v1(144.78,45.85) v1(144.78,41.53) v1(144.91,135.13) v1(144.91,112.24) v1(144.91,111.61) v1(144.91,72.14) v1(144.91,71.5) v1(145.03,97.85) v1(145.03,93.34) v1(144.97,67.69) v1(145.16,120.14) v1(145.16,92.01) v1(145.16,74.3) v1(145.16,73.66) v1(145.16,50.29) v1(145.41,52.45) v1(145.48,89.6) v1(145.67,106.81) v1(145.67,48.51) v1(145.67,44.2) v1(145.67,43.56) v1(145.85,30.88) v1(145.92,72.14) v1(145.92,71.5) v1(145.99,122.3) v1(146.11,123.95) v1(146.11,85.28) v1(146.05,50.29) v1(146.13,36.32) v1(146.24,107.12) v1(146.18,99.44) v1(146.18,38.04) v1(146.18,37.34) v1(146.3,112.78) v1(146.3,97.76) v1(146.3,48.51) v1(146.3,43.56) v1(146.53,91.82) v1(146.56,135.13) v1(146.56,71.63) v1(146.56,58.93) v1(146.71,105.36) v1(146.75,85.28) v1(146.69,65.28) v1(146.69,50.29) v1(146.94,97.79) v1(146.94,73.28) v1(146.94,48.51) v1(146.94,47.88) v1(147,104.1) v1(147.07,125.09) v1(147.11,94.69) v1(147.07,90.3) v1(147.07,89.66) v1(147.2,103.49) v1(147.24,96.22) v1(147.26,123.89) v1(147.26,122.3) v1(147.32,117.98) v1(147.32,113.79) v1(147.32,52.45) v1(147.38,85.28) v1(147.57,99.31) v1(147.57,47.88) v1(147.83,103.89) v1(147.83,102.11) v1(147.83,92.02) v1(148.02,85.92) v1(148.02,85.28) v1(148.08,93.34) v1(148.08,23.11) v1(148.08,20.7) v1(148.21,33.02) v1(148.21,29.84) v1(148.34,46.35) v1(148.59,125.09) v1(148.64,90.42) v1(148.72,93.34) v1(148.72,92.02) v1(148.81,95.1) v1(148.84,38.73) v1(148.87,97.89) v1(148.95,89.87) v1(148.91,85.92) v1(148.91,85.28) v1(148.97,135.13) v1(148.97,113.79) v1(148.97,40.26) v1(149.1,71.12) v1(149.1,37.97) v1(149.22,36.58) v1(149.22,35.81) v1(149.33,93.17) v1(149.35,105.16) v1(149.61,60.2) v1(149.61,58.93) v1(149.67,68.07) v1(149.73,37.97) v1(149.86,111.76) v1(149.86,97.92) v1(149.88,76.76) v1(149.88,76) v1(149.86,39.5) v1(149.99,105.16) v1(149.99,85.47) v1(149.99,28.57) v1(149.99,27.94) v1(149.99,21.97) v1(150.24,32.52) v1(150.25,30.22) v1(150.37,77.19) v1(150.37,75.59) v1(150.55,124.97) v1(150.5,39.5) v1(150.61,135.2) v1(150.62,101.09) v1(150.58,95.1) v1(150.66,104.05) v1(150.74,88.43) v1(150.79,99.61) v1(150.89,97.79) v1(151,34.8) v1(151,34.16) v1(151.13,39.5) v1(151.18,93.17) v1(151.38,47.5) v1(151.38,36.32) v1(151.38,35.69) v1(151.74,103.53) v1(151.7,99.6) v1(151.83,67.56) v1(151.89,78.87) v1(151.89,78.11) v1(151.89,23.24) v1(151.89,20.7) v1(152.02,113.79) v1(151.96,106.05) v1(152.04,97.82) v1(152.02,36.32) v1(152.02,35.69) v1(152.15,92.79) v1(152.23,54.65) v1(152.27,87.25) v1(152.27,57.66) v1(152.53,78.87) v1(152.53,78.11) v1(152.62,25.78) v1(152.78,119.76) v1(152.91,135.13) v1(152.96,67.44) v1(152.98,45.85) v1(153.18,132.33) v1(153.23,124.97) v1(153.16,78.87) v1(153.16,78.11) v1(153.42,122.38) v1(153.54,112.52) v1(153.67,88.77) v1(153.8,119.74) v1(153.8,93.22) v1(153.99,128.02) v1(154.1,75.31) v1(154.06,73.47) v1(154.05,72.39) v1(154.08,65.18) v1(154.18,135.18) v1(154.18,117.73) v1(154.18,74.36) v1(154.18,61.85) v1(154.18,60.45) v1(154.18,59.82) v1(154.18,59.18) v1(154.31,63.63) v1(154.43,25.4) v1(154.43,24.74) v1(154.43,24) v1(154.56,62.87) v1(154.69,105.92) v1(154.75,94.87) v1(154.72,73.46) v1(154.74,72.46) v1(154.69,69.72) v1(154.77,75.28) v1(154.81,74.36) v1(154.81,66.42) v1(154.81,64.64) v1(154.81,61.85) v1(154.81,60.46) v1(154.81,59.82) v1(154.81,59.18) v1(154.86,67.87) v1(155.07,92.01) v1(155.07,51.56) v1(155.18,132.34) v1(155.32,105.92) v1(155.26,71.37) v1(155.51,56.83) v1(155.7,108.2) v1(155.77,127.97) v1(155.85,135.18) v1(155.96,105.92) v1(155.99,39.62) v1(156.18,122.45) v1(156.21,115.7) v1(156.34,88.58) v1(156.44,111.76) v1(156.97,35.43) v1(157.1,32.27) v1(157.23,116.71) v1(157.23,116.08) v1(157.23,74.93) v1(157.23,65.28) v1(157.23,62.36) v1(157.56,70.87) v1(157.67,41.53) v1(157.67,40.7) v1(158.12,87.12) v1(158.12,86.49) v1(158.24,20.83) v1(158.5,132.33) v1(158.5,63.37) v1(158.5,62.74) v1(158.62,135.13) v1(158.62,89.66) v1(158.62,89.03) v1(158.7,93.27) v1(158.75,128.02) v1(158.75,94.69) v1(158.94,98.74) v1(158.94,98.04) v1(159.13,124.46) v1(159.13,70.61) v1(159.13,40.64) v1(159.26,44.7) v1(159.38,61.21) v1(159.51,54.5) v1(159.64,48.39) v1(159.89,90.55) v1(160.4,54.55) v1(160.4,50.55) v1(160.66,107.06) v1(160.66,46.86) v1(161.04,44.7) v1(161.29,129.16) v1(161.48,54.61) v1(161.61,62.48) v1(161.67,98.55) v1(161.67,76.17) v1(161.67,73.53) v1(161.67,72.9) v1(161.67,70.99) v1(161.8,74.8) v1(161.93,37.59) v1(161.98,70.34) v1(161.98,69.71) v1(161.98,68.82) v1(161.98,68.15) v1(162.18,54.61) v1(162.27,36.2) v1(162.5,70.74) v1(162.81,54.74) v1(162.94,32.18) v1(163.03,48.64) v1(163.07,43.18) v1(163.39,93.66) v1(163.51,108.2) v1(163.58,37.59) v1(163.68,106.48) v1(163.68,105.41) v1(163.7,48.64) v1(163.83,102.62) v1(163.83,99.44) v1(163.77,97.85) v1(163.86,104.14) v1(164.13,80.9) v1(164.18,132.36) v1(164.21,42.29) v1(164.29,111.38) v1(164.72,54.74) v1(164.85,104.65) v1(164.85,96.42) v1(164.85,92.2) v1(164.91,100.84) v1(164.91,99.44) v1(164.91,94.87) v1(164.97,97.92) v1(164.97,94.21) v1(164.97,74.04) v1(164.97,58.67) v1(164.97,57.86) v1(165.18,128.02) v1(165.42,103.06) v1(165.42,102.36) v1(165.35,54.74) v1(165.51,76.46) v1(165.61,79.63) v1(165.61,77.09) v1(165.68,37.65) v1(166.18,135.31) v1(166.18,128.02) v1(166.37,24.51) v1(166.64,137.78) v1(166.62,29.34) v1(166.88,81.15) v1(167.13,24.51) v1(167.18,132.28) v1(167.18,128.02) v1(167.26,51.94) v1(167.26,50.29) v1(167.39,74.04) v1(167.39,48.9) v1(167.64,34.42) v1(167.64,29.34) v1(168,97.9) v1(168.02,96.4) v1(167.99,94.9) v1(168.02,92.2) v1(168.02,66.46) v1(168.02,64.96) v1(168.1,99.4) v1(168.15,71.5) v1(168.15,70.87) v1(168.15,69.6) v1(168.15,65.79) v1(168.15,63.63) v1(168.15,59.86) v1(168.15,59.05) v1(168.15,37.72) v1(168.15,37.08) v1(168.18,132.33) v1(168.18,127.98) v1(168.28,24.51) v1(168.43,119.28) v1(168.4,104.78) v1(168.4,91.69) v1(168.4,91.06) v1(168.4,88.39) v1(168.4,87.76) v1(168.4,87.12) v1(168.4,86.49) v1(168.53,102.3) v1(168.66,66.45) v1(168.76,135.99) v1(168.78,100.9) v1(168.78,71.5) v1(168.78,70.87) v1(168.85,68.77) v1(168.78,29.34) v1(169.04,24.51) v1(169.18,135.24) v1(169.18,128.02) v1(169.48,112.46) v1(169.54,93.34) v1(169.54,77.72) v1(169.54,77.09) v1(169.93,105.73) v1(169.93,34.42) v1(169.93,29.34) v1(170.18,119.51) v1(170.18,118.87) v1(170.18,77.72) v1(170.18,77.09) v1(170.56,31.75) v1(170.69,120.9) v1(170.7,60.47) v1(170.81,56.01) v1(170.94,108.64) v1(170.94,89.03) v1(171.15,96.93) v1(171.07,96.08) v1(171.07,94.55) v1(171.07,83.31) v1(171.07,33.15) v1(171.2,119.51) v1(171.2,98.55) v1(171.32,120.9) v1(171.32,42.29) v1(171.65,108.46) v1(171.65,107.7) v1(171.58,25.02) v1(171.7,33.15) v1(171.96,120.9) v1(172.09,107.19) v1(172.18,125.09) v1(172.21,70.55) v1(172.21,69.91) v1(172.34,33.15) v1(172.59,120.9) v1(172.72,118.62) v1(172.72,117.98) v1(172.85,82.68) v1(172.85,81.66) v1(172.95,112.24) v1(172.92,38.25) v1(172.97,61.21) v1(172.97,59.94) v1(172.97,58.67) v1(172.97,57.4) v1(173.23,24.13) v1(173.23,22.48) v1(173.23,20.57) v1(173.41,111.79) v1(173.35,30.23) v1(173.61,58.67) v1(173.74,82.17) v1(173.74,41.67) v1(173.8,68.83) v1(173.8,66.99) v1(173.79,29.16) v1(173.91,38.23) v1(173.99,118.68) v1(173.99,117.98) v1(173.99,53.59) v1(173.99,52.45) v1(174.62,82.68) v1(174.62,81.66) v1(174.75,24.13) v1(174.75,22.48) v1(174.75,20.57) v1(174.75,1.52) v1(175.01,136.27) v1(175.01,121.92) v1(175.01,121.16) v1(175.01,49.78) v1(175.13,137.03) v1(175.13,71.5) v1(175.13,70.36) v1(175.13,67.69) v1(175.37,44.21) v1(175.82,30.45) v1(175.9,87.63) v1(175.9,87) v1(175.9,86.36) v1(176.28,24.13) v1(176.28,22.48) v1(176.28,20.57) v1(176.53,87.63) v1(176.53,87) v1(176.53,86.36) v1(176.53,51.94) v1(176.53,48.13) v1(176.63,36.7) v1(176.91,111.76) v1(176.91,108.58) v1(176.91,105.16) v1(176.91,65.15) v1(177.23,72.33) v1(177.23,69.72) v1(177.23,68.77) v1(177.3,54.35) v1(177.42,116.9) v1(177.42,116.27) v1(177.55,36.7) v1(177.61,27.88) v1(178.05,116.9) v1(178.05,116.27) v1(178.18,121.92) v1(178.18,121.16) v1(178.44,51.31) v1(178.82,131.83) v1(178.82,130.94) v1(178.82,130.05) v1(178.94,121.34) v1(179.07,29.59) v1(179.32,108.58) v1(179.43,103.94) v1(179.5,123.37) v1(179.45,111.7) v1(179.45,105.28) v1(179.58,121.28) v1(179.71,29.59) v1(179.83,131.83) v1(179.83,130.94) v1(179.83,130.05) v1(179.83,72.77) v1(179.83,70.99) v1(179.83,69.09) v1(179.96,110.49) v1(180.04,104.91) v1(180.04,104.14) v1(180.34,29.59) v1(180.34,1.52) v1(180.72,113.01) v1(180.72,112.25) v1(180.87,110.93) v1(180.97,118.62) v1(180.97,29.59) v1(181.1,72.77) v1(181.1,70.99) v1(181.23,69.09) v1(181.36,113.03) v1(181.36,112.27) v1(181.36,12.19) v1(181.36,11.56) v1(181.36,10.92) v1(181.36,10.16) v1(181.36,9.4) v1(181.46,109.68) v1(181.46,108.53) v1(182.07,109.48) v1(182.07,108.72) v1(182.12,10.92) v1(182.12,10.16) v1(182.12,9.4) v1(182.37,1.52) v1(182.5,72.77) v1(182.5,70.99) v1(182.88,105.79) v1(183.39,89.41) v1(183.39,88.65) v1(183.39,87.88) v1(184.28,89.41) v1(184.28,88.65) v1(184.28,87.88) v1(184.91,109.09) v1(185.42,106.05) v1(185.42,81.28) v1(188.47,85.85) v1(188.47,80.77) v1(188.47,69.09) v1(188.47,64.52) v1(188.47,44.2) v1(188.47,39.12) v1(188.47,25.4) v1(188.47,19.3) v1(188.47,13.21) v1(188.47,7.11) v1(188.47,1.52) v2(60.07,25.4) v2(60.71,25.15) v2(61.34,27.69) v2(61.49,41.38) v2(61.47,38.48) v2(61.47,35.56) v2(61.85,29.72) v2(62.38,38.48) v2(62.61,41.27) v2(62.87,26.8) v2(62.99,24) v2(63.25,36.2) v2(63.37,30.73) v2(63.63,34.54) v2(64.06,38.48) v2(64.06,36.7) v2(64.52,43.18) v2(64.52,34.92) v2(64.77,40.89) v2(64.77,27.81) v2(64.9,29.84) v2(65.02,31.75) v2(65.28,24) v2(65.53,41.66) v2(65.51,35.18) v2(65.63,43.1) v2(65.91,45.97) v2(65.91,33.53) v2(65.94,32.13) v2(65.91,27.81) v2(66.55,44.96) v2(66.55,41.02) v2(66.67,35.23) v2(66.8,33.78) v2(67.18,30.1) v2(67.44,26.67) v2(67.44,24) v2(69.09,30.23) v2(69.42,34.42) v2(69.47,31.11) v2(69.6,26.67) v2(69.6,24) v2(70.36,27.05) v2(70.36,26.04) v2(70.48,34.92) v2(70.87,29.72) v2(71.88,24) v2(72.52,27.81) v2(73.03,31.62) v2(73.53,29.84) v2(73.79,28.07) v2(74.04,24) v2(75.06,30.61) v2(75.44,29.34) v2(76.2,29.97) v2(76.2,24) v2(76.71,25.65) v2(78.49,25.65) v2(93.9,136.55) v2(94.43,128.16) v2(94.94,128.16) v2(95.2,136.53) v2(97.99,136.53) v2(98.43,128.33) v2(98.94,128.33) v2(99.29,136.53) v2(102.82,113.26) v2(103.21,113.25) v2(103.72,113.25) v2(104.11,113.23) v2(104.32,111.76) v2(104.72,118.84) v2(104.72,111.76) v2(105.23,118.84) v2(105.23,111.76) v2(105.61,111.76) v2(106.65,32.98) v2(106.64,31.48) v2(106.83,42.16) v2(107.04,32.45) v2(107.04,31.47) v2(107.84,32.45) v2(107.84,31.47) v2(107.83,24.59) v2(108.15,42.16) v2(108.24,31.45) v2(108.33,118.75) v2(108.34,24.59) v2(108.64,32.27) v2(108.71,118.8) v2(108.71,114.41) v2(109.22,118.8) v2(109.22,114.41) v2(109.34,24.59) v2(109.6,118.75) v2(109.84,24.59) v2(111.39,24.59) v2(111.9,24.59) v2(112.17,31.45) v2(112.64,32.45) v2(112.64,31.47) v2(112.89,24.59) v2(113.03,112.47) v2(113.03,111.96) v2(113.44,112.47) v2(113.44,111.96) v2(113.44,32.45) v2(113.44,31.47) v2(113.4,24.59) v2(113.71,118.47) v2(113.69,118.08) v2(113.91,31.46) v2(114.22,118.47) v2(114.22,118.08) v2(114.81,118.47) v2(115.21,118.46) v2(115.72,118.46) v2(115.72,45.55) v2(116.51,118.16) v2(116.6,112.71) v2(116.6,112.2) v2(117.01,45.55) v2(117.81,118.16) v2(118.11,112.98) v2(118.47,112.78) v2(118.97,112.78) v2(119.71,113.18) v2(120.22,113.18) v2(120.62,113.18) v2(121.21,116.22) v2(121.51,113.28) v2(121.51,112.04) v2(121.63,112.91) v2(121.63,112.41) v2(121.72,116.22) v2(122.73,118.92) v2(123.23,118.92) v2(123.41,125.06) v2(123.67,112.71) v2(123.67,112.2) v2(123.67,111.81) v2(123.72,96.52) v2(123.84,135.25) v2(123.92,125.06) v2(124.35,135.25) v2(124.97,96.52) v2(125.37,118.1) v2(125.5,112.61) v2(125.5,112.1) v2(125.73,112.93) v2(125.83,111.89) v2(125.88,118.1) v2(127.43,124.56) v2(127.82,135.25) v2(127.94,124.56) v2(128.33,135.25) v2(129.8,122.46) v2(129.8,121.95) v2(130.18,120.81) v2(130.18,120.3) v2(131.43,125.17) v2(131.79,135.25) v2(131.94,125.17) v2(132.21,119.63) v2(132.21,119.13) v2(132.3,135.25) v2(134.6,124.04) v2(135.11,124.04) v2(135.48,135.51) v2(135.78,135.25) v2(136.29,135.25) v2(139.34,123.78) v2(139.85,123.78) v2(141.38,135.38) v2(141.8,135.38) v2(142.31,135.38) v2(143.11,93.87) v2(143.11,93.36) v2(143.33,123.78) v2(143.83,123.78) v2(144.4,65.47) v2(145.48,135.38) v2(145.92,65.47) v2(145.99,135.38) v2(146.41,123.49) v2(146.39,121.93) v2(146.92,123.49) v2(146.89,121.93) v2(146.94,66.74) v2(149.57,135.38) v2(150.08,135.38) v2(153.52,120.78) v2(153.64,121.92) v2(154.54,67.47) v2(154.54,66.96) v2(154.78,135.38) v2(154.81,122.94) v2(155.29,135.38) v2(155.96,121.92) v2(156.08,120.78) v2(163.4,92.63) v2(163.63,96.29) v2(163.63,95) v2(170.99,100.84) v2(170.99,99.54) v2(170.98,97.98) v2(170.98,97.47) v2(170.98,95.57) v2(170.98,95.06) v2(171.7,70.45) v2(171.7,69.94) v2(171.83,103.82) v2(171.81,103.42) v2(171.81,102.91) v2(171.83,102.49) v2(173.35,68.58) v2(173.35,68.16) v2(173.35,67.65) v2(173.35,67.25) v3(93.9,136.55) v3(94.43,128.16) v3(94.94,128.16) v3(95.2,136.53) v3(97.99,136.53) v3(98.43,128.33) v3(98.94,128.33) v3(99.29,136.53) v3(102.82,113.26) v3(103.21,113.25) v3(103.72,113.25) v3(104.11,113.23) v3(104.32,111.76) v3(104.72,118.84) v3(104.72,111.76) v3(105.23,118.84) v3(105.23,111.76) v3(105.61,111.76) v3(106.65,32.98) v3(106.64,31.48) v3(106.83,42.16) v3(107.04,32.45) v3(107.04,31.47) v3(107.84,32.45) v3(107.84,31.47) v3(107.83,24.59) v3(108.15,42.16) v3(108.23,33.07) v3(108.24,31.45) v3(108.33,118.75) v3(108.34,24.59) v3(108.64,32.27) v3(108.71,118.8) v3(108.71,114.41) v3(109.22,118.8) v3(109.22,114.41) v3(109.34,24.59) v3(109.6,118.75) v3(109.84,24.59) v3(109.86,99.95) v3(110.01,102.13) v3(110.01,93.14) v3(110.29,99.95) v3(110.44,104.17) v3(111.1,97.71) v3(111.1,91.62) v3(111.39,24.59) v3(111.81,105.18) v3(111.9,24.59) v3(112.17,31.45) v3(112.64,32.45) v3(112.64,31.47) v3(112.89,24.59) v3(113.03,112.47) v3(113.03,111.96) v3(113.44,112.47) v3(113.44,111.96) v3(113.44,32.45) v3(113.44,31.47) v3(113.4,24.59) v3(113.46,93.5) v3(113.71,118.47) v3(113.69,118.08) v3(113.91,31.46) v3(114.22,118.47) v3(114.22,118.08) v3(114.5,95.22) v3(114.81,118.47) v3(115.21,118.46) v3(115.72,118.46) v3(115.72,45.55) v3(116.51,118.16) v3(116.6,112.71) v3(116.6,112.2) v3(117.01,45.55) v3(117.81,118.16) v3(118.11,112.98) v3(118.47,112.78) v3(118.97,112.78) v3(119.71,113.18) v3(120.22,113.18) v3(120.62,113.18) v3(121.21,116.22) v3(121.51,113.28) v3(121.51,112.04) v3(121.63,112.91) v3(121.63,112.41) v3(121.72,116.22) v3(122.73,118.92) v3(123.23,118.92) v3(123.41,125.06) v3(123.67,112.71) v3(123.67,112.2) v3(123.67,111.81) v3(123.72,96.52) v3(123.84,135.25) v3(123.92,125.06) v3(124.35,135.25) v3(124.46,95.55) v3(124.46,91.72) v3(124.97,96.52) v3(125.37,118.1) v3(125.5,112.61) v3(125.5,112.1) v3(125.73,112.93) v3(125.83,111.89) v3(125.88,118.1) v3(126.5,96.17) v3(126.49,93.85) v3(127.43,124.56) v3(127.82,135.25) v3(127.94,124.56) v3(128.33,135.25) v3(128.52,91.68) v3(129.8,122.46) v3(129.8,121.95) v3(130.18,120.81) v3(130.18,120.3) v3(130.51,93.83) v3(131.43,125.17) v3(131.79,135.25) v3(131.94,125.17) v3(132.21,119.63) v3(132.21,119.13) v3(132.3,135.25) v3(134.6,124.04) v3(135.11,124.04) v3(135.48,135.51) v3(135.78,135.25) v3(136.29,135.25) v3(139.34,123.78) v3(139.45,92.39) v3(139.85,123.78) v3(140.68,93) v3(141.25,95.02) v3(141.38,135.38) v3(141.8,135.38) v3(142.31,135.38) v3(142.75,60.58) v3(143.11,93.87) v3(143.11,93.36) v3(143.19,60.58) v3(143.33,123.78) v3(143.83,123.78) v3(145.48,135.38) v3(145.99,135.38) v3(146.41,123.49) v3(146.39,121.93) v3(146.92,123.49) v3(146.89,121.93) v3(149.57,135.38) v3(150.08,135.38) v3(153.52,121.54) v3(153.52,121.16) v3(153.52,120.78) v3(153.64,121.92) v3(154.54,67.47) v3(154.54,66.96) v3(154.78,135.38) v3(154.81,122.94) v3(154.94,50.8) v3(155.29,135.38) v3(155.96,121.92) v3(156.06,121.54) v3(156.06,121.16) v3(156.08,120.78) v3(157.99,81.66) v3(163.4,92.63) v3(163.63,96.29) v3(163.63,95) v3(170.99,100.84) v3(170.99,99.54) v3(170.98,97.98) v3(170.98,97.47) v3(170.98,95.57) v3(170.98,95.06) v3(171.7,70.45) v3(171.7,69.94) v3(171.83,103.82) v3(171.81,103.42) v3(171.81,102.91) v3(171.83,102.49) v3(173.35,68.58) v3(173.35,68.16) v3(173.35,67.65) v3(173.35,67.25) v5(65.66,36.8) v5(66.04,36.7) v5(70.41,20.19) v5(70.92,20.19) v5(71.32,20.19) v5(72.49,20.27) v5(72.92,20.27) v5(73.43,20.27) v5(88.54,18.35) v5(89.05,18.35) v5(90.82,18.34) v5(91.33,18.34) v5(104.09,95.05) v5(104.35,91.82) v5(104.6,92.13) v5(104.86,91.82) v5(105.08,93.55) v5(105.26,94.79) v5(105.45,93.54) v5(105.46,90.42) v5(105.71,90.73) v5(105.94,95.53) v5(105.96,93.54) v5(106.05,91.95) v5(105.97,90.42) v5(106.32,93.55) v5(106.71,99.64) v5(106.65,95.02) v5(106.81,101.6) v5(106.81,100.46) v5(107.05,99.43) v5(107.55,99.43) v5(107.75,98.06) v5(107.77,100.56) v5(107.77,94.67) v5(107.95,99.44) v5(108.15,98.06) v5(108.15,94.57) v5(108.41,93.85) v5(108.49,96.55) v5(108.65,98.06) v5(108.66,94.57) v5(108.66,92.54) v5(108.79,100.71) v5(109.04,94.54) v5(109.12,98.07) v5(109.39,102.2) v5(109.36,99.04) v5(109.37,93.01) v5(109.58,96.93) v5(109.8,104.06) v5(109.76,103.05) v5(109.75,102.07) v5(109.76,99.06) v5(109.76,94.05) v5(109.75,93.07) v5(110.26,102.07) v5(110.27,99.06) v5(110.26,93.07) v5(110.44,97.61) v5(110.44,94.49) v5(110.46,100.56) v5(110.46,91.57) v5(110.64,102.11) v5(110.64,93.04) v5(110.66,99.04) v5(110.85,97.6) v5(110.85,100.57) v5(110.86,94.58) v5(110.85,91.56) v5(111,101.73) v5(111.07,104.06) v5(111.12,100.08) v5(111.18,105.08) v5(111.25,90.68) v5(111.36,101.54) v5(111.36,100.57) v5(111.36,98.57) v5(111.35,97.6) v5(111.36,95.54) v5(111.37,94.58) v5(111.36,92.54) v5(111.36,91.56) v5(111.56,105.08) v5(111.73,97.61) v5(111.81,105.84) v5(111.76,100.58) v5(111.81,99.57) v5(111.75,94.59) v5(111.76,91.57) v5(112.06,105.08) v5(112.06,102.11) v5(112.06,96.04) v5(112.06,93.09) v5(112.45,102.12) v5(112.46,100.05) v5(112.46,96.06) v5(112.46,94.05) v5(112.45,93.07) v5(112.46,91.05) v5(112.96,102.12) v5(112.97,96.06) v5(112.96,93.07) v5(113.11,99.62) v5(113.23,103.57) v5(113.16,100.84) v5(113.18,96.52) v5(113.16,94.61) v5(113.16,91.57) v5(113.36,102.11) v5(113.36,96.04) v5(113.36,93.07) v5(113.53,103.81) v5(113.55,100.81) v5(113.56,96.52) v5(113.56,94.56) v5(113.55,91.58) v5(113.79,97.03) v5(113.79,91.19) v5(114.04,103.81) v5(114.05,100.81) v5(114.07,96.52) v5(114.07,94.56) v5(114.06,92.54) v5(114.06,91.58) v5(114.33,103.53) v5(114.45,100.81) v5(114.45,96.52) v5(114.45,94.59) v5(114.45,91.49) v5(114.68,97.66) v5(114.68,92.71) v5(114.81,93.73) v5(115.19,102.3) v5(115.16,91.05) v5(115.57,76.96) v5(115.87,97.66) v5(115.86,95.54) v5(116.26,97.64) v5(116.54,97.03) v5(116.76,97.64) v5(117.22,97.79) v5(117.16,95.54) v5(117.16,92.54) v5(117.47,93.09) v5(117.47,89.15) v5(117.6,95.5) v5(117.86,97.05) v5(117.86,94.05) v5(117.86,91.05) v5(118.24,102.49) v5(118.24,99.95) v5(119.16,97.05) v5(119.16,94.05) v5(119.38,99.31) v5(119.44,97.54) v5(119.86,104.54) v5(119.87,102.44) v5(119.86,101.54) v5(119.86,95.54) v5(119.86,92.54) v5(119.96,99.57) v5(120.27,104.65) v5(120.25,102.42) v5(120.25,99.3) v5(120.25,93.03) v5(120.4,82.17) v5(120.52,99.69) v5(120.52,92.71) v5(120.65,84.01) v5(120.76,102.42) v5(120.76,99.3) v5(120.76,93.03) v5(120.93,93.42) v5(120.97,94.68) v5(121.06,99.57) v5(121.16,104.54) v5(121.16,102.44) v5(121.16,97.47) v5(121.54,105.79) v5(121.84,103.94) v5(121.86,103.05) v5(121.87,100.94) v5(121.86,97.05) v5(122.05,96.01) v5(122.05,94.69) v5(122.05,83.06) v5(122.05,81.22) v5(122.1,89.94) v5(122.25,103.97) v5(122.25,90.3) v5(122.5,104.27) v5(122.76,103.97) v5(122.81,96.01) v5(122.76,90.3) v5(122.91,89.94) v5(123.04,94.74) v5(123.14,100.94) v5(123.19,104.01) v5(123.16,103.05) v5(123.83,100.71) v5(123.83,91.52) v5(123.86,101.54) v5(123.86,95.54) v5(123.9,94.77) v5(124.03,99.49) v5(124.08,105.79) v5(124.24,91.59) v5(124.34,104.44) v5(124.25,104.05) v5(124.25,100.71) v5(124.25,94.59) v5(124.51,100.41) v5(124.75,91.59) v5(124.65,78.23) v5(124.71,76.33) v5(124.71,74.55) v5(124.76,104.05) v5(124.76,100.71) v5(124.76,94.59) v5(124.84,79.12) v5(124.9,77.28) v5(124.9,75.44) v5(124.9,73.66) v5(124.97,103.71) v5(125.12,105.66) v5(125.12,100.58) v5(125.09,99.09) v5(125.12,94.77) v5(125.15,91.57) v5(125.16,95.54) v5(125.16,92.54) v5(125.4,100.13) v5(125.45,97.36) v5(125.86,101.02) v5(125.87,98.07) v5(125.88,96.22) v5(125.86,93.07) v5(126.11,105.03) v5(126.11,103.38) v5(126.25,105.4) v5(126.25,101.01) v5(126.25,96.07) v5(126.25,93.07) v5(126.76,105.4) v5(126.76,101.01) v5(126.76,96.07) v5(126.76,93.07) v5(126.9,105.03) v5(126.87,102.62) v5(127.15,101.02) v5(127.17,98.05) v5(127.15,96.06) v5(127.84,100.84) v5(127.76,91.44) v5(127.79,67.98) v5(127.86,102.49) v5(127.86,95.54) v5(127.89,94.81) v5(127.99,105.77) v5(128.25,102.53) v5(128.25,100.67) v5(128.25,94.62) v5(128.25,91.57) v5(128.3,67.98) v5(128.65,103.63) v5(128.76,102.53) v5(128.76,100.67) v5(128.76,94.62) v5(128.76,91.57) v5(128.91,104.01) v5(129.1,94.81) v5(129.16,102.6) v5(129.16,100.71) v5(129.16,95.54) v5(129.16,91.57) v5(129.87,99.19) v5(129.87,96.19) v5(129.87,93.04) v5(130.05,102.29) v5(130.25,102.62) v5(130.25,99.07) v5(130.25,96.08) v5(130.25,93.07) v5(130.68,105.03) v5(130.66,103) v5(130.76,102.62) v5(130.76,99.07) v5(130.76,96.08) v5(130.76,93.07) v5(131.14,99.19) v5(131.17,105.54) v5(131.17,96.06) v5(131.17,93.09) v5(131.56,105.54) v5(131.83,105.16) v5(131.83,99.57) v5(131.88,102.54) v5(131.88,99.06) v5(131.86,96.56) v5(131.97,91.84) v5(132.07,105.54) v5(132.25,98.96) v5(132.28,92.08) v5(132.25,90.17) v5(132.44,105.66) v5(132.46,100.33) v5(132.76,98.96) v5(132.79,92.08) v5(132.76,90.17) v5(133.15,99.06) v5(133.15,96.57) v5(133.22,102.16) v5(133.16,92.54) v5(133.17,91.95) v5(133.86,97.05) v5(133.86,91.05) v5(134.81,92.14) v5(135.16,97.05) v5(135.16,91.05) v5(135.38,101.73) v5(135.86,101.54) v5(135.86,97.66) v5(136.08,93.47) v5(136.08,92.14) v5(136.4,103.25) v5(136.5,90.83) v5(136.65,105.54) v5(137.16,101.54) v5(137.16,97.66) v5(137.35,93.47) v5(137.62,101.83) v5(137.76,84.9) v5(137.92,105.16) v5(137.88,96.2) v5(137.86,91.05) v5(138.18,104.01) v5(138.3,105.79) v5(138.25,96.08) v5(138.76,96.08) v5(138.94,105.28) v5(138.94,104.01) v5(139.09,102.03) v5(139.1,84.9) v5(139.16,97.05) v5(139.17,96.09) v5(139.16,91.05) v5(139.73,102.02) v5(139.83,105.79) v5(139.85,103.89) v5(139.86,101.54) v5(139.85,94.59) v5(139.86,92.54) v5(139.87,91.58) v5(140.27,96.84) v5(140.25,94.58) v5(140.25,91.58) v5(140.46,103.5) v5(140.72,102.44) v5(140.84,96.01) v5(140.76,94.58) v5(140.76,91.58) v5(141.05,103.61) v5(141.02,92.58) v5(141.15,94.56) v5(141.15,91.58) v5(141.86,105.18) v5(141.91,103.66) v5(141.86,97.54) v5(141.86,97.05) v5(141.86,91.05) v5(142.04,91.69) v5(142.25,103.47) v5(142.25,105.17) v5(142.25,97.38) v5(142.37,103) v5(142.76,105.17) v5(142.75,103.47) v5(142.76,97.38) v5(142.98,96.55) v5(143.13,97.54) v5(143.16,106.05) v5(143.15,105.18) v5(143.15,103.56) v5(143.15,92.08) v5(143.89,102.74) v5(143.99,98.76) v5(144.09,96.22) v5(145.16,99.06) v5(146.33,91.34) v5(147.88,104.85) v5(148.34,94.87) v5(148.36,103.89) v5(148.36,101.04) v5(148.59,105.28) v5(148.75,102.52) v5(148.97,94.36) v5(149.22,102.51) v5(149.54,99.06) v5(149.9,96.6) v5(150.62,101.79) v5(151.26,99.28) v5(154.55,122.34) v5(154.75,102.04) v5(155.06,122.34) v5(156.72,108.33) v5(156.72,107.44) v5(157.1,108.14) v5(157.1,107.63) v5(163.13,84.07) v5(164.72,106.59) v5(164.72,105.28) v5(180.38,111.28) v5(180.38,110.78) v5(183.08,111.35) v5(183.08,110.84) v5(183.41,111.56) v5(183.44,110.67) v6(45.09,10.54) v6(45.85,9.78) v6(46.35,12.45) v6(47.24,32.64) v6(47.75,18.29) v6(47.75,14.22) v6(47.75,12.57) v6(47.75,11.18) v6(49.02,34.42) v6(49.02,17.91) v6(49.02,14.48) v6(49.15,31.62) v6(50.04,33.53) v6(50.04,12.57) v6(50.04,10.92) v6(50.29,17.27) v6(50.29,14.61) v6(50.29,9.27) v6(50.42,20.19) v6(50.93,32.26) v6(51.05,36.45) v6(51.31,7.37) v6(51.69,25.65) v6(51.82,22.35) v6(51.94,35.31) v6(52.32,31.75) v6(52.7,33.78) v6(52.7,9.78) v6(52.83,37.21) v6(52.83,18.8) v6(52.83,13.72) v6(52.83,11.05) v6(52.96,16.38) v6(53.59,21.08) v6(54.23,42.55) v6(54.23,36.58) v6(54.74,35.43) v6(54.74,21.46) v6(54.99,22.61) v6(55.37,34.67) v6(55.5,41.53) v6(56.39,22.48) v6(56.64,41.53) v6(56.77,37.47) v6(57.02,36.2) v6(57.53,43.69) v6(57.91,41.53) v6(58.42,39.12) v6(58.67,37.85) v6(59.05,41.53) v6(59.56,44.58) v6(60.2,41.53) v6(60.33,38.61) v6(60.58,44.2) v6(61.34,41.53) v6(61.72,39.37) v6(61.98,42.67) v6(62.61,44.7) v6(62.61,41.53) v6(62.61,38.61) v6(62.99,42.67) v6(63.5,44.07) v6(63.75,40.51) v6(65.66,36.8) v6(66.04,36.7) v6(70.41,20.19) v6(70.92,20.19) v6(71.32,20.19) v6(72.49,20.27) v6(72.92,20.27) v6(73.43,20.27) v6(88.54,18.35) v6(89.05,18.35) v6(90.82,18.34) v6(91.33,18.34) v6(94.26,95.54) v6(95.16,98.54) v6(95.35,100.05) v6(95.36,97.05) v6(99.66,98.54) v6(99.66,95.54) v6(100.56,101.55) v6(100.76,103.05) v6(101.46,104.54) v6(104.09,95.05) v6(104.36,100.05) v6(104.36,97.05) v6(104.36,94.05) v6(104.35,91.82) v6(104.86,91.82) v6(105.08,93.55) v6(105.26,94.79) v6(105.45,93.54) v6(105.46,90.42) v6(105.94,95.53) v6(105.96,101.54) v6(105.96,98.54) v6(105.96,93.54) v6(105.96,92.54) v6(105.97,90.42) v6(106.32,93.55) v6(106.71,99.64) v6(106.65,95.02) v6(107.05,99.43) v6(107.06,103.05) v6(107.06,100.05) v6(107.06,97.05) v6(107.06,94.05) v6(107.06,91.05) v6(107.55,99.43) v6(107.75,98.06) v6(107.76,104.54) v6(107.77,100.56) v6(107.77,94.67) v6(107.95,99.44) v6(108.15,98.06) v6(108.15,94.57) v6(108.49,96.55) v6(108.66,101.54) v6(108.66,98.54) v6(108.65,98.06) v6(108.66,95.54) v6(108.66,94.57) v6(108.66,92.54) v6(108.79,100.71) v6(109.04,94.54) v6(109.12,98.07) v6(109.39,102.2) v6(109.36,99.04) v6(109.37,93.01) v6(109.58,96.93) v6(109.76,106.05) v6(109.8,104.06) v6(109.76,103.05) v6(109.75,102.07) v6(109.76,100.05) v6(109.76,99.06) v6(109.76,94.05) v6(109.75,93.07) v6(109.76,91.05) v6(110.26,102.07) v6(110.27,99.06) v6(110.26,93.07) v6(110.44,97.61) v6(110.44,94.49) v6(110.46,104.54) v6(110.46,100.56) v6(110.46,91.57) v6(110.64,102.11) v6(110.64,93.04) v6(110.66,99.04) v6(110.85,97.6) v6(110.85,100.57) v6(110.86,94.58) v6(110.85,91.56) v6(111.07,104.06) v6(111.18,105.08) v6(111.36,101.54) v6(111.36,100.57) v6(111.36,98.57) v6(111.35,97.6) v6(111.36,95.54) v6(111.37,94.58) v6(111.36,92.54) v6(111.36,91.56) v6(111.56,105.08) v6(111.73,97.61) v6(111.76,100.58) v6(111.81,99.57) v6(111.75,94.59) v6(111.76,91.57) v6(112.06,105.08) v6(112.06,102.11) v6(112.06,96.04) v6(112.06,93.09) v6(112.45,105.08) v6(112.46,106.05) v6(112.46,103.05) v6(112.45,102.12) v6(112.46,100.05) v6(112.46,97.05) v6(112.46,96.06) v6(112.46,94.05) v6(112.45,93.07) v6(112.46,91.05) v6(112.96,102.12) v6(112.97,96.06) v6(112.96,93.07) v6(113.11,99.62) v6(113.16,104.54) v6(113.23,103.57) v6(113.16,100.84) v6(113.18,96.52) v6(113.16,94.61) v6(113.16,91.57) v6(113.36,102.11) v6(113.36,96.04) v6(113.36,93.07) v6(113.53,103.81) v6(113.55,100.81) v6(113.56,96.52) v6(113.56,94.56) v6(113.55,91.58) v6(114.04,103.81) v6(114.06,104.54) v6(114.06,101.54) v6(114.05,100.81) v6(114.06,98.54) v6(114.07,96.52) v6(114.06,95.54) v6(114.07,94.56) v6(114.06,92.54) v6(114.06,91.58) v6(114.33,103.53) v6(114.45,100.81) v6(114.45,96.52) v6(114.45,94.59) v6(114.45,91.49) v6(114.68,97.66) v6(115.16,106.05) v6(115.16,103.05) v6(115.16,100.05) v6(115.16,97.05) v6(115.16,94.05) v6(115.16,91.05) v6(115.86,104.54) v6(115.86,101.54) v6(115.86,98.54) v6(115.87,97.66) v6(115.86,95.54) v6(115.86,92.54) v6(116.26,97.64) v6(116.76,97.64) v6(117.16,104.54) v6(117.16,101.54) v6(117.16,98.54) v6(117.22,97.79) v6(117.16,95.54) v6(117.16,92.54) v6(117.86,106.05) v6(117.86,103.05) v6(117.86,100.05) v6(117.86,97.05) v6(117.86,94.05) v6(117.86,91.05) v6(119.16,106.05) v6(119.16,103.05) v6(119.16,100.05) v6(119.16,97.05) v6(119.16,94.05) v6(119.16,91.05) v6(119.86,104.54) v6(119.87,102.44) v6(119.86,101.54) v6(119.86,98.54) v6(119.86,95.54) v6(119.86,92.54) v6(119.96,99.57) v6(120.25,102.42) v6(120.25,99.3) v6(120.25,93.03) v6(120.52,92.71) v6(120.76,102.42) v6(120.76,99.3) v6(120.76,93.03) v6(120.93,93.42) v6(121.06,99.57) v6(121.16,104.54) v6(121.16,102.44) v6(121.16,101.54) v6(121.16,98.54) v6(121.16,95.54) v6(121.16,92.54) v6(121.84,103.94) v6(121.86,106.05) v6(121.86,103.05) v6(121.87,100.94) v6(121.86,100.05) v6(121.86,97.05) v6(121.86,94.05) v6(121.86,91.05) v6(122.05,94.69) v6(122.1,89.94) v6(122.25,103.97) v6(122.25,90.3) v6(122.76,103.97) v6(122.76,90.3) v6(122.91,89.94) v6(123.04,94.74) v6(123.14,100.94) v6(123.16,106.05) v6(123.19,104.01) v6(123.16,103.05) v6(123.16,100.05) v6(123.16,97.05) v6(123.16,94.05) v6(123.16,91.05) v6(123.83,100.71) v6(123.83,91.52) v6(123.86,104.54) v6(123.86,101.54) v6(123.86,98.54) v6(123.86,95.54) v6(123.9,94.77) v6(123.86,92.54) v6(124.03,99.49) v6(124.24,91.59) v6(124.34,104.44) v6(124.25,104.05) v6(124.25,100.71) v6(124.25,94.59) v6(124.75,91.59) v6(124.76,104.05) v6(124.76,100.71) v6(124.76,94.59) v6(124.97,103.71) v6(125.12,100.58) v6(125.09,99.09) v6(125.12,94.77) v6(125.15,91.57) v6(125.16,104.54) v6(125.16,101.54) v6(125.16,98.54) v6(125.16,95.54) v6(125.16,92.54) v6(125.45,97.36) v6(125.86,106.05) v6(125.86,103.05) v6(125.86,101.02) v6(125.86,100.05) v6(125.87,98.07) v6(125.86,97.05) v6(125.88,96.22) v6(125.86,94.05) v6(125.86,93.07) v6(125.86,91.05) v6(126.11,105.03) v6(126.25,105.4) v6(126.25,101.01) v6(126.25,96.07) v6(126.25,93.07) v6(126.76,105.4) v6(126.76,101.01) v6(126.76,96.07) v6(126.76,93.07) v6(126.9,105.03) v6(127.16,106.05) v6(127.16,103.05) v6(127.15,101.02) v6(127.16,100.05) v6(127.17,98.05) v6(127.16,97.05) v6(127.15,96.06) v6(127.16,94.05) v6(127.16,91.05) v6(127.84,100.84) v6(127.76,91.44) v6(127.79,67.98) v6(127.86,104.54) v6(127.86,102.49) v6(127.86,101.54) v6(127.86,98.54) v6(127.86,95.54) v6(127.89,94.81) v6(127.86,92.54) v6(128.25,102.53) v6(128.25,100.67) v6(128.25,94.62) v6(128.25,91.57) v6(128.3,67.98) v6(128.76,102.53) v6(128.76,100.67) v6(128.76,94.62) v6(128.76,91.57) v6(128.91,104.01) v6(129.1,94.81) v6(129.16,104.54) v6(129.16,102.6) v6(129.16,101.54) v6(129.16,100.71) v6(129.16,98.54) v6(129.16,95.54) v6(129.16,92.54) v6(129.16,91.57) v6(129.86,106.05) v6(129.86,103.05) v6(129.86,100.05) v6(129.87,99.19) v6(129.86,97.05) v6(129.87,96.19) v6(129.86,94.05) v6(129.87,93.04) v6(129.86,91.05) v6(130.05,102.29) v6(130.25,102.62) v6(130.25,99.07) v6(130.25,96.08) v6(130.25,93.07) v6(130.66,103) v6(130.76,102.62) v6(130.76,99.07) v6(130.76,96.08) v6(130.76,93.07) v6(131.14,99.19) v6(131.16,106.05) v6(131.17,105.54) v6(131.16,103.05) v6(131.16,100.05) v6(131.16,97.05) v6(131.17,96.06) v6(131.16,94.05) v6(131.17,93.09) v6(131.16,91.05) v6(131.56,105.54) v6(131.86,104.54) v6(131.88,102.54) v6(131.86,101.54) v6(131.88,99.06) v6(131.86,98.54) v6(131.86,96.56) v6(131.86,95.54) v6(131.86,92.54) v6(131.97,91.84) v6(132.07,105.54) v6(132.25,98.96) v6(132.28,92.08) v6(132.25,90.17) v6(132.44,105.66) v6(132.76,98.96) v6(132.79,92.08) v6(132.76,90.17) v6(133.15,99.06) v6(133.15,96.57) v6(133.16,104.54) v6(133.22,102.16) v6(133.16,101.54) v6(133.16,98.54) v6(133.16,95.54) v6(133.16,92.54) v6(133.17,91.95) v6(133.86,106.05) v6(133.86,103.05) v6(133.86,100.05) v6(133.86,97.05) v6(133.86,94.05) v6(133.86,91.05) v6(135.16,106.05) v6(135.16,103.05) v6(135.16,100.05) v6(135.16,97.05) v6(135.16,94.05) v6(135.16,91.05) v6(135.86,104.54) v6(135.86,101.54) v6(135.86,98.54) v6(135.86,97.66) v6(135.86,95.54) v6(135.86,92.54) v6(136.5,90.83) v6(137.16,104.54) v6(137.16,101.54) v6(137.16,98.54) v6(137.16,97.66) v6(137.16,95.54) v6(137.16,92.54) v6(137.62,101.83) v6(137.76,84.9) v6(137.86,106.05) v6(137.86,103.07) v6(137.86,100.05) v6(137.86,97.05) v6(137.88,96.2) v6(137.86,94.05) v6(137.86,91.05) v6(138.25,96.08) v6(138.76,96.08) v6(139.09,102.03) v6(139.1,84.9) v6(139.16,106.05) v6(139.16,103.05) v6(139.16,100.05) v6(139.16,97.05) v6(139.17,96.09) v6(139.16,94.05) v6(139.16,91.05) v6(139.73,102.02) v6(139.86,104.54) v6(139.85,103.89) v6(139.86,101.54) v6(139.86,98.54) v6(139.86,95.54) v6(139.85,94.59) v6(139.86,92.54) v6(139.87,91.58) v6(140.25,94.58) v6(140.25,91.58) v6(140.72,102.44) v6(140.76,94.58) v6(140.76,91.58) v6(141.05,103.61) v6(141.02,92.58) v6(141.15,94.56) v6(141.15,91.58) v6(141.16,104.54) v6(141.16,101.54) v6(141.16,98.54) v6(141.16,95.54) v6(141.86,106.05) v6(141.86,105.18) v6(141.91,103.66) v6(141.86,103.05) v6(141.86,100.05) v6(141.86,97.54) v6(141.86,97.05) v6(141.86,91.05) v6(142.04,91.69) v6(142.25,103.47) v6(142.25,105.17) v6(142.25,97.38) v6(142.76,105.17) v6(142.75,103.47) v6(142.76,97.38) v6(142.98,96.55) v6(143.13,97.54) v6(143.16,106.05) v6(143.15,105.18) v6(143.15,103.56) v6(143.16,103.05) v6(143.16,100.05) v6(143.15,92.08) v6(143.16,91.05) v6(143.86,104.54) v6(143.86,101.54) v6(143.99,98.76) v6(144.09,96.22) v6(145.16,99.06) v6(145.86,100.05) v6(145.86,97.05) v6(145.86,91.05) v6(146.33,91.34) v6(147.19,85.98) v6(147.46,101.54) v6(147.46,98.54) v6(147.46,95.54) v6(147.46,92.54) v6(147.88,104.85) v6(148.34,94.87) v6(148.36,103.89) v6(148.36,101.04) v6(148.59,105.28) v6(148.75,102.52) v6(148.97,94.36) v6(149.22,102.51) v6(149.54,99.06) v6(149.9,96.6) v6(150.16,98.54) v6(150.62,101.79) v6(151.26,99.28) v6(154.24,85.47) v6(154.55,122.34) v6(154.75,102.04) v6(155.06,122.34) v6(156.72,108.33) v6(156.72,107.44) v6(157.1,108.14) v6(157.1,107.63) v6(163.13,84.07) v6(164.72,106.59) v6(164.72,105.28) v6(180.38,111.28) v6(180.38,110.78) v6(183.08,111.35) v6(183.08,110.84) v6(183.41,111.56) v6(183.44,110.67) v7(61.92,18.8) v7(62.58,18.8) v7(62.99,19.94) v7(64.26,40.44) v7(64.34,18.41) v7(64.36,17.88) v7(64.36,17.21) v7(64.39,16.66) v7(65.53,17.65) v7(65.53,17.09) v7(66.07,17.7) v7(66.07,17.04) v7(67.18,16.64) v7(67.75,16.64) v7(68.41,16.64) v7(68.91,16.87) v7(70.92,18.81) v7(70.97,18.26) v7(71.58,18.81) v7(71.6,18.26) v7(72.26,18.29) v7(72.44,35.31) v7(72.43,18.82) v7(73.09,18.82) v7(73.25,18.29) v7(75.09,18.29) v7(75.06,17.65) v7(75.69,17.65) v7(75.75,18.29) v7(76.28,17.65) v7(76.61,18.29) v7(77.27,18.29) v7(77.85,18.03) v7(78.54,40.64) v7(78.54,39.98) v7(79.07,40.64) v7(79.07,40.11) v7(79.63,40.64) v7(80.03,40.23) v7(80.03,39.57) v7(80.47,39.88) v7(81.15,41.38) v7(81.6,40.96) v7(81.6,40.3) v7(81.61,39.75) v7(82.49,42.04) v7(82.75,40.49) v7(82.93,41.66) v7(82.93,41) v7(83.49,39.75) v7(83.52,38.33) v7(99.31,20.32) v7(107.06,33.78) v7(107.84,36.27) v7(107.89,34.73) v7(107.87,33.81) v7(108.46,38.99) v7(108.64,37.07) v7(108.64,35.47) v7(108.61,33.82) v7(108.69,33.02) v7(108.71,31.43) v7(109.44,36.27) v7(109.44,32.27) v7(109.47,33.91) v7(110.21,38.61) v7(110.24,35.47) v7(110.22,33.89) v7(110.74,38.61) v7(111,32.26) v7(111,31.5) v7(111.7,31.37) v7(111.84,37.87) v7(111.84,36.27) v7(111.84,32.27) v7(111.88,35.43) v7(111.86,33.91) v7(111.86,33.02) v7(112.7,33.85) v7(114.17,36.2) v7(114.78,112.55) v7(114.83,91.77) v7(116.03,112.9) v7(116.05,112.37) v7(116.18,118.49) v7(116.38,113.31) v7(119.25,113.21) v7(119.81,90.4) v7(121.21,90.4) v7(123.72,118.8) v7(131.64,102.11) v7(131.67,96.11) v7(133.32,96.14) v7(144.19,89.64) v7(144.85,89.64) v7(145.16,55.12) v7(145.29,94.61) v7(150.62,91.87) v7(151.23,90.09) v7(153.95,120.32) v7(154.57,69.04) v7(154.57,68.38) v7(155.65,120.32) v7(176.15,26.54)
